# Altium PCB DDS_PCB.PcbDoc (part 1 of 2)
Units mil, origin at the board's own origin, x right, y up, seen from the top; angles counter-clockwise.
Board outline 3998.07 x 3476.44 mil, 8 copper layers (TOP_L1, Plane_L2, Inner_L3, Plane_L4, Plane_L5, Inner_L6, Plane_L7, Bottom Layer_L8), stack 26.8 mil thick; 404 components, 274 nets, 1325 pads, 24 vias.
Unrouted connection lines stored in the file: 923.
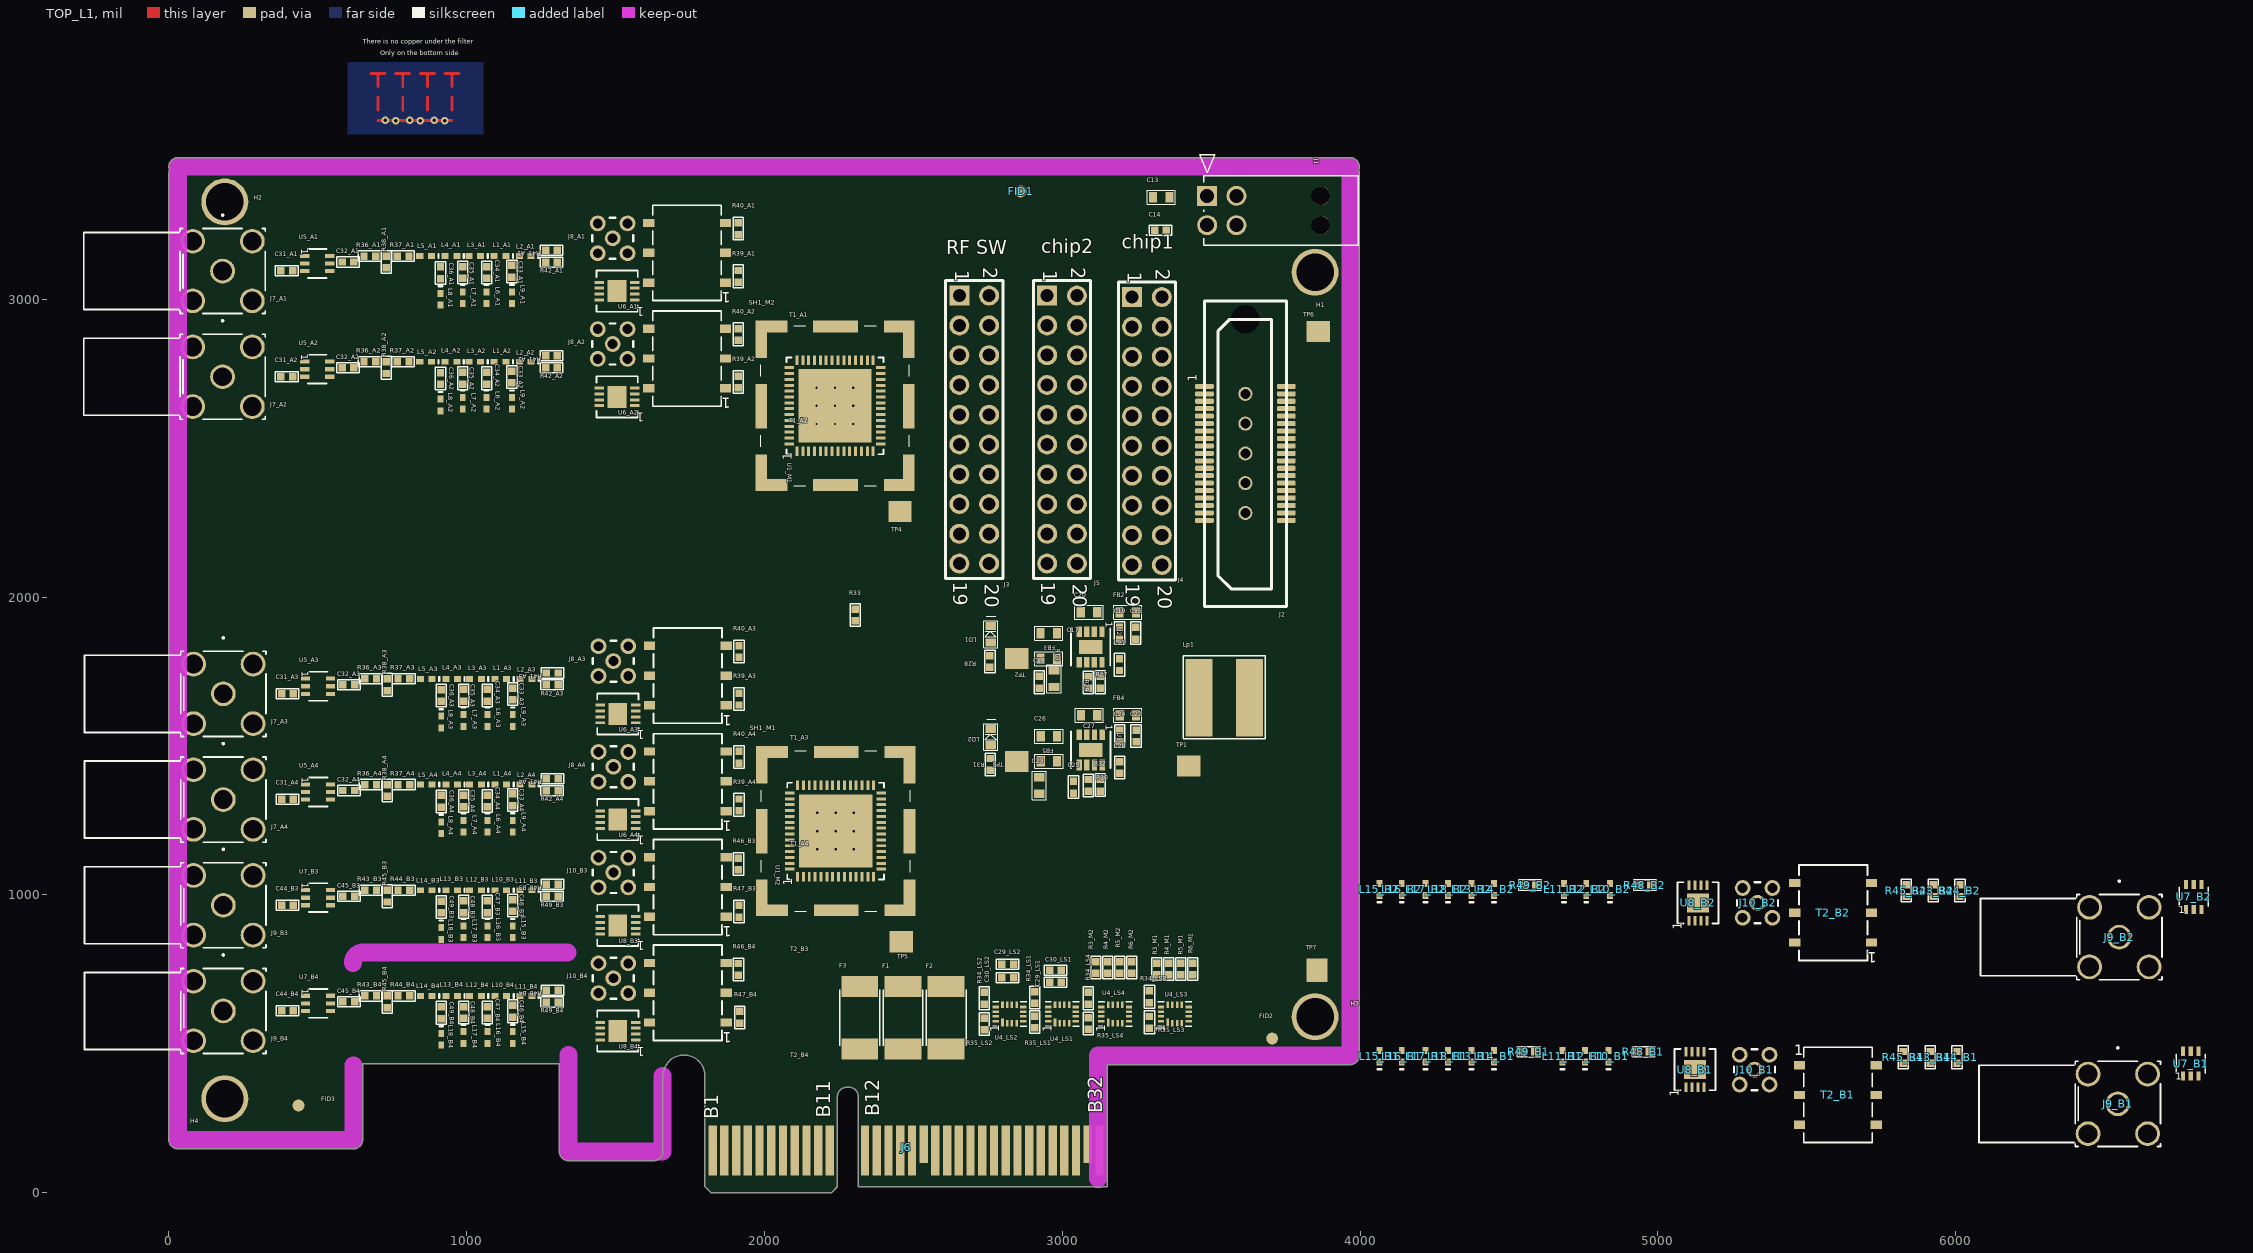
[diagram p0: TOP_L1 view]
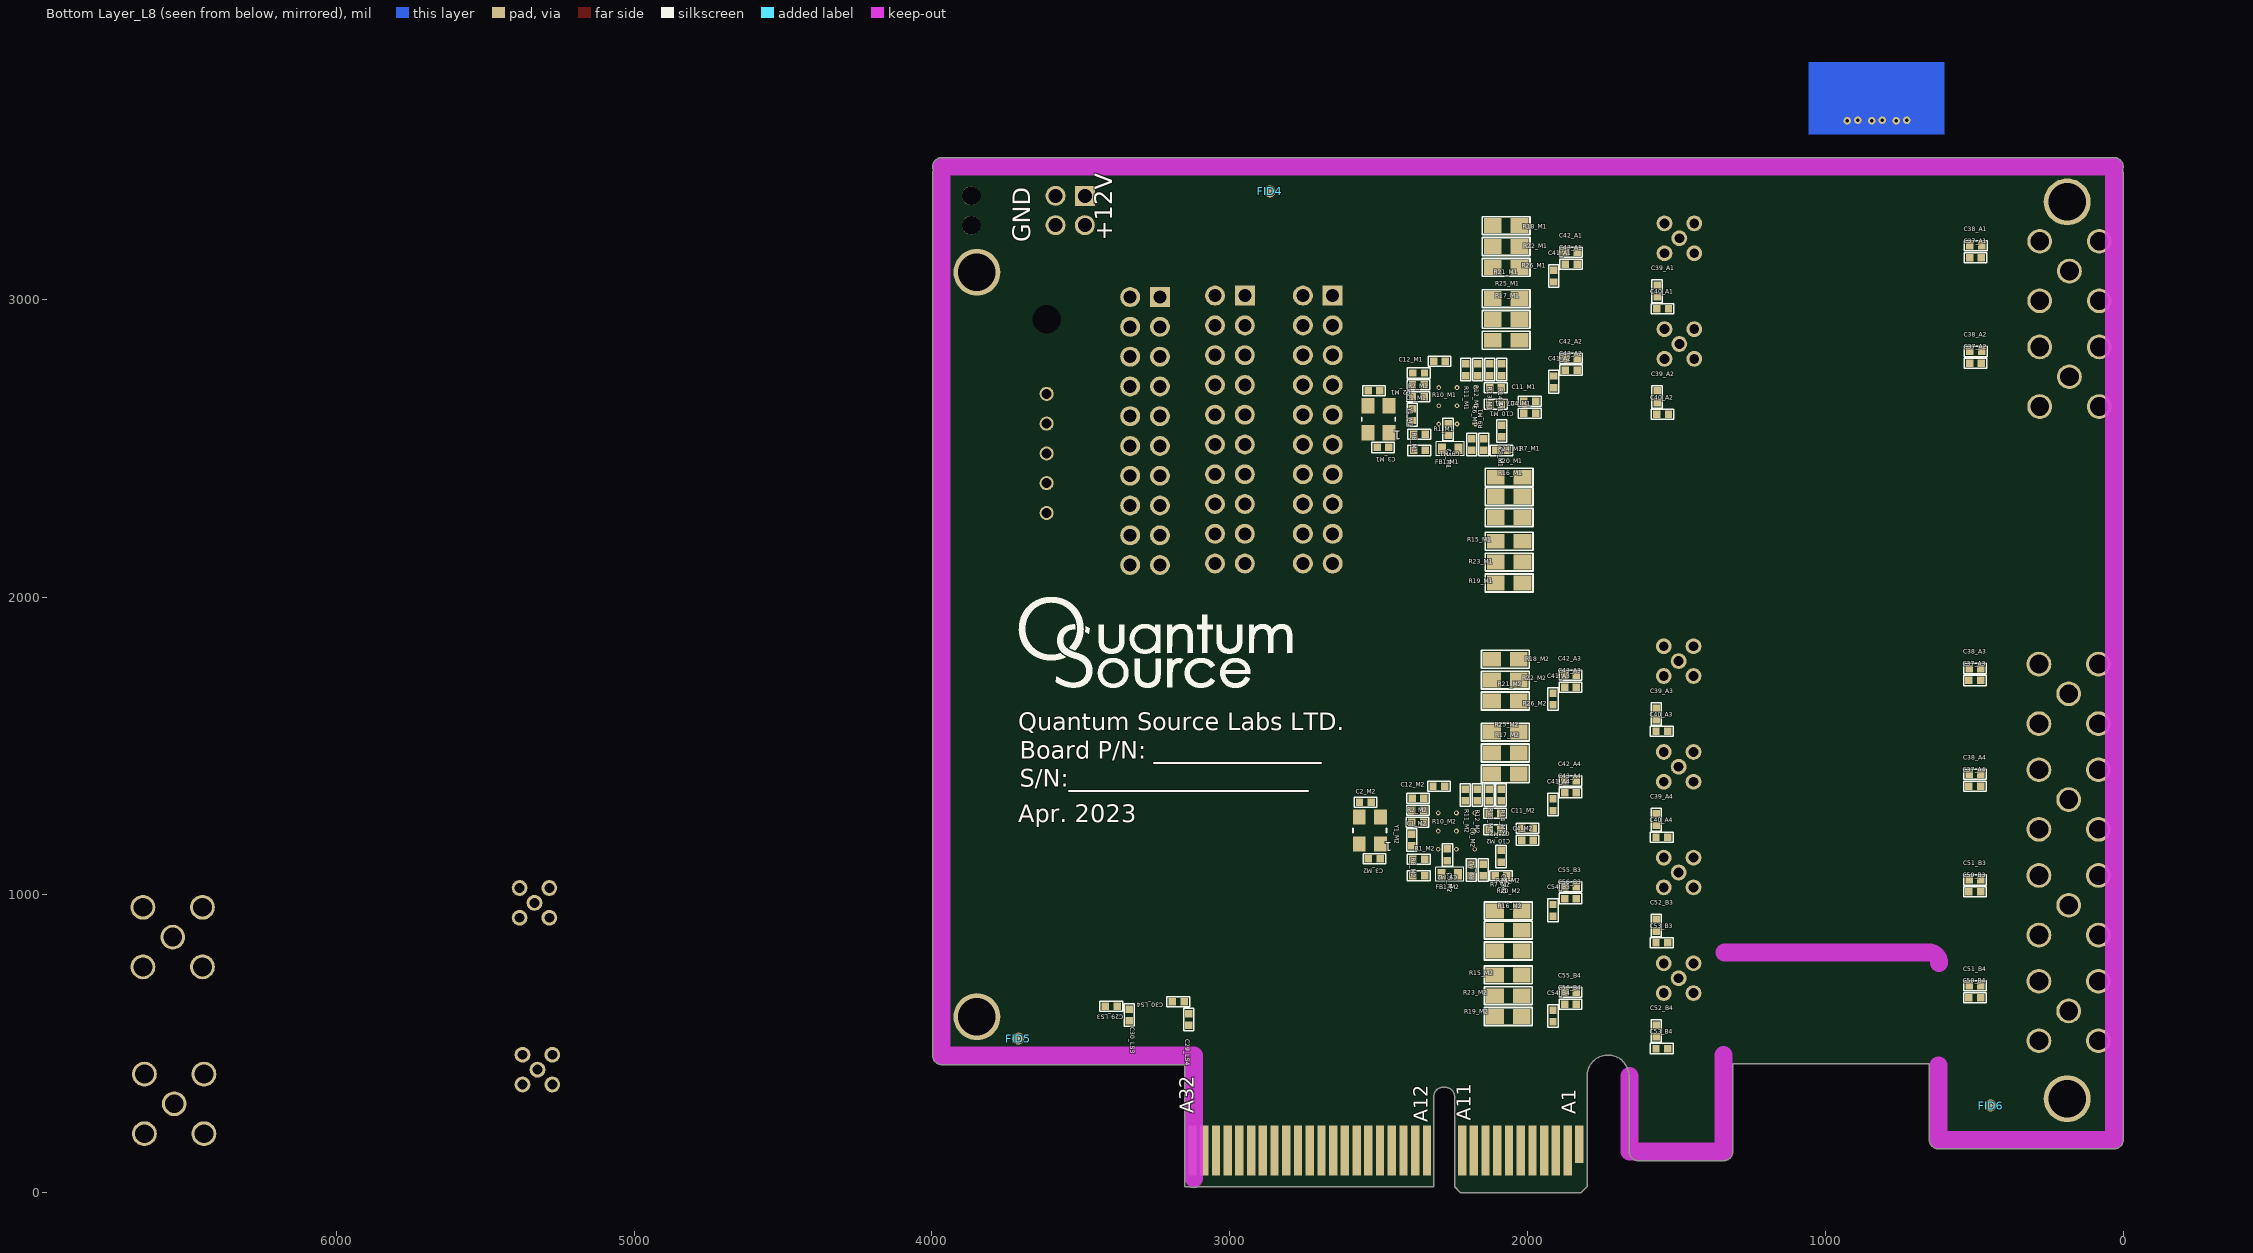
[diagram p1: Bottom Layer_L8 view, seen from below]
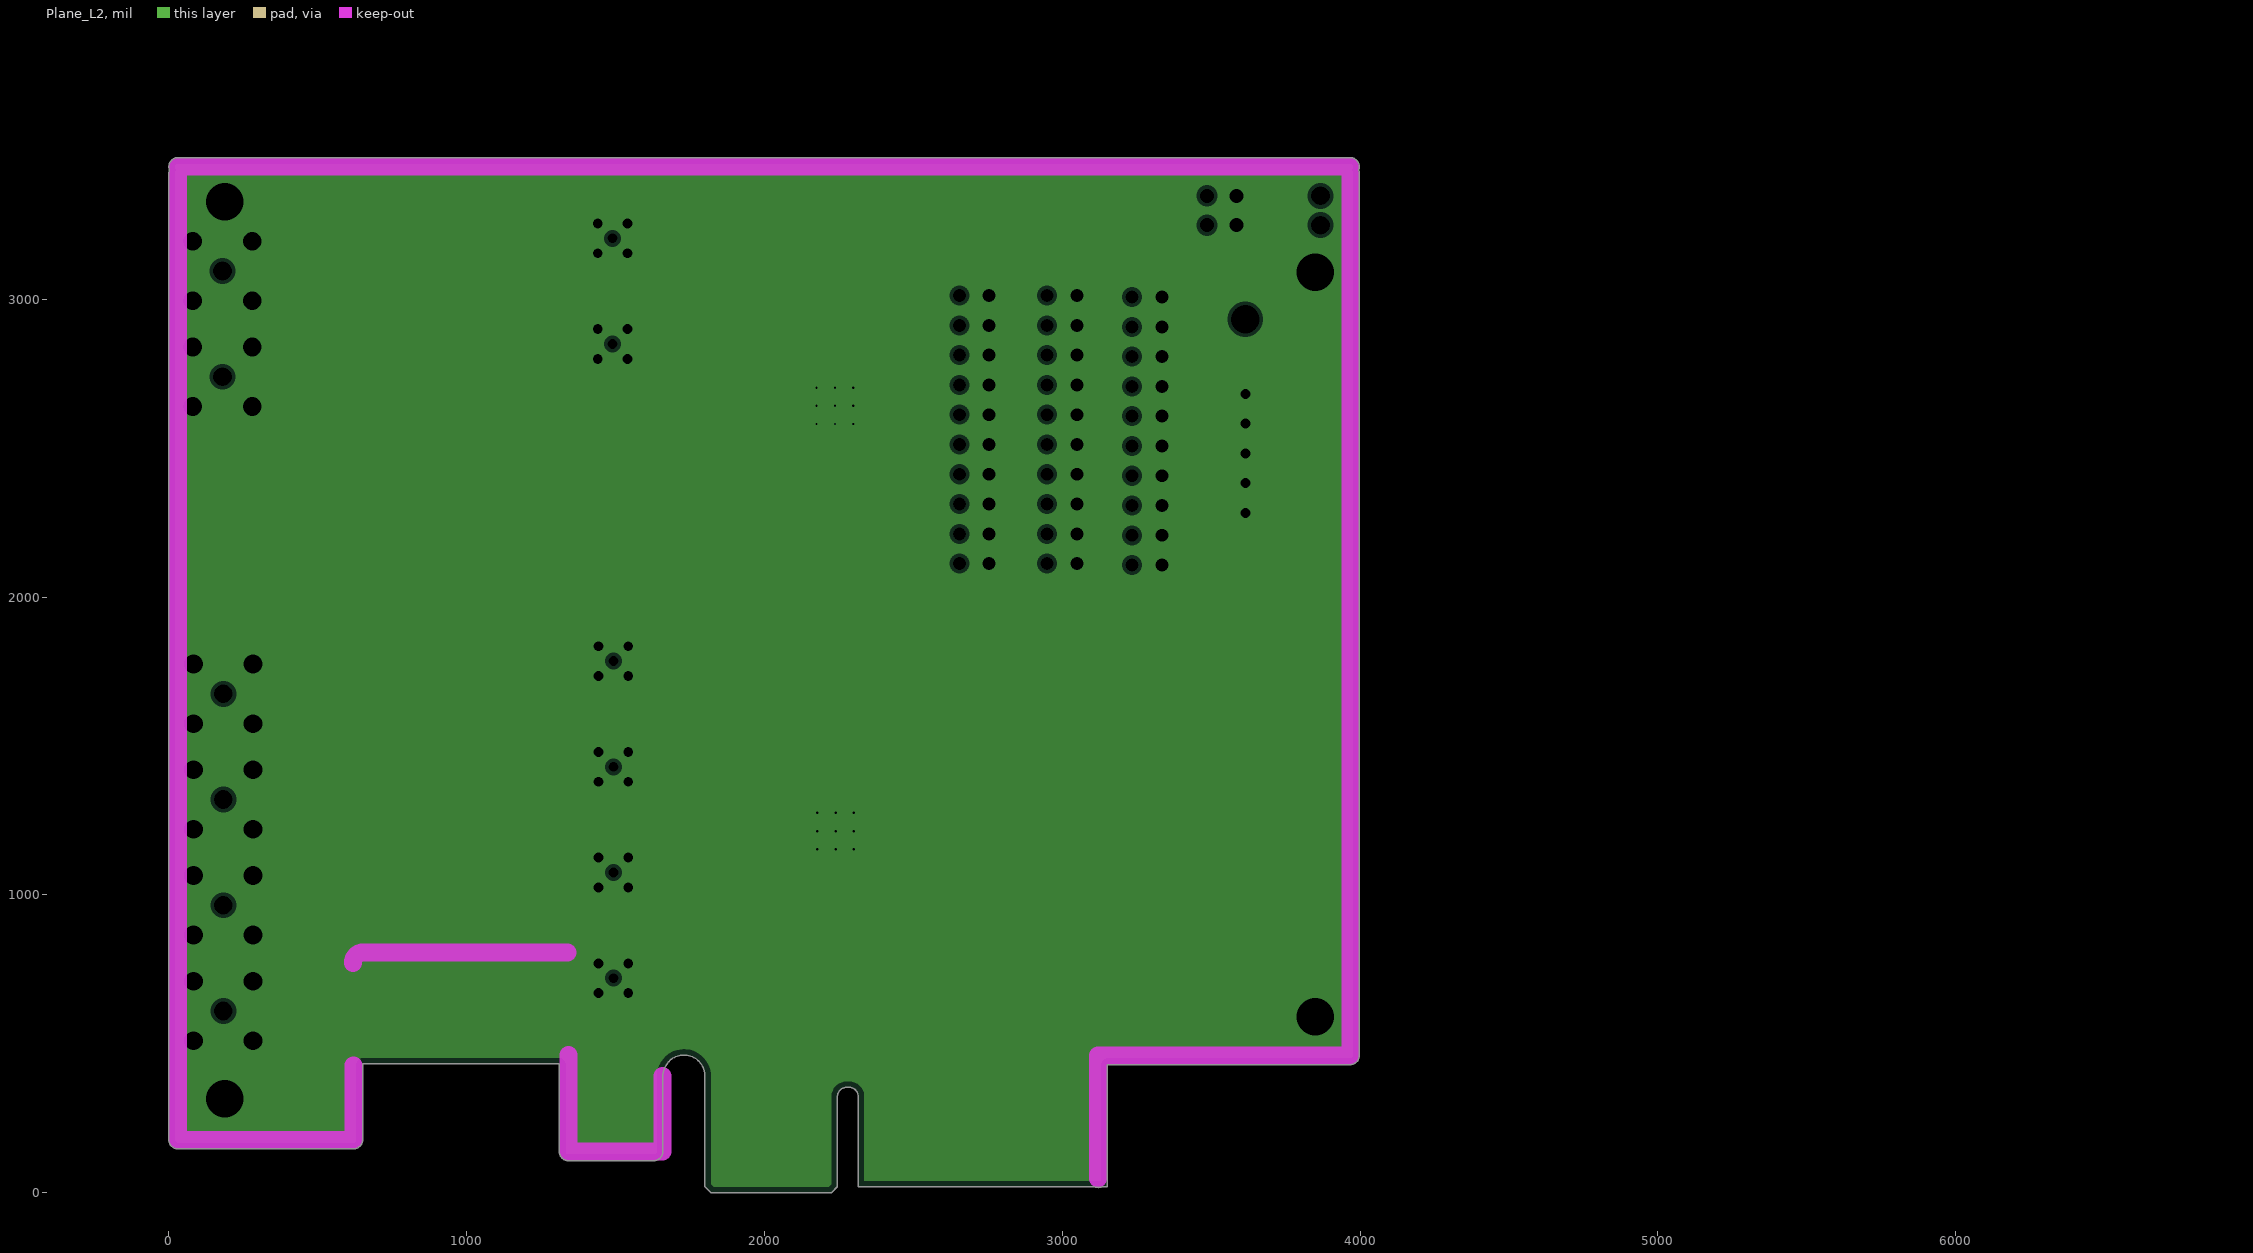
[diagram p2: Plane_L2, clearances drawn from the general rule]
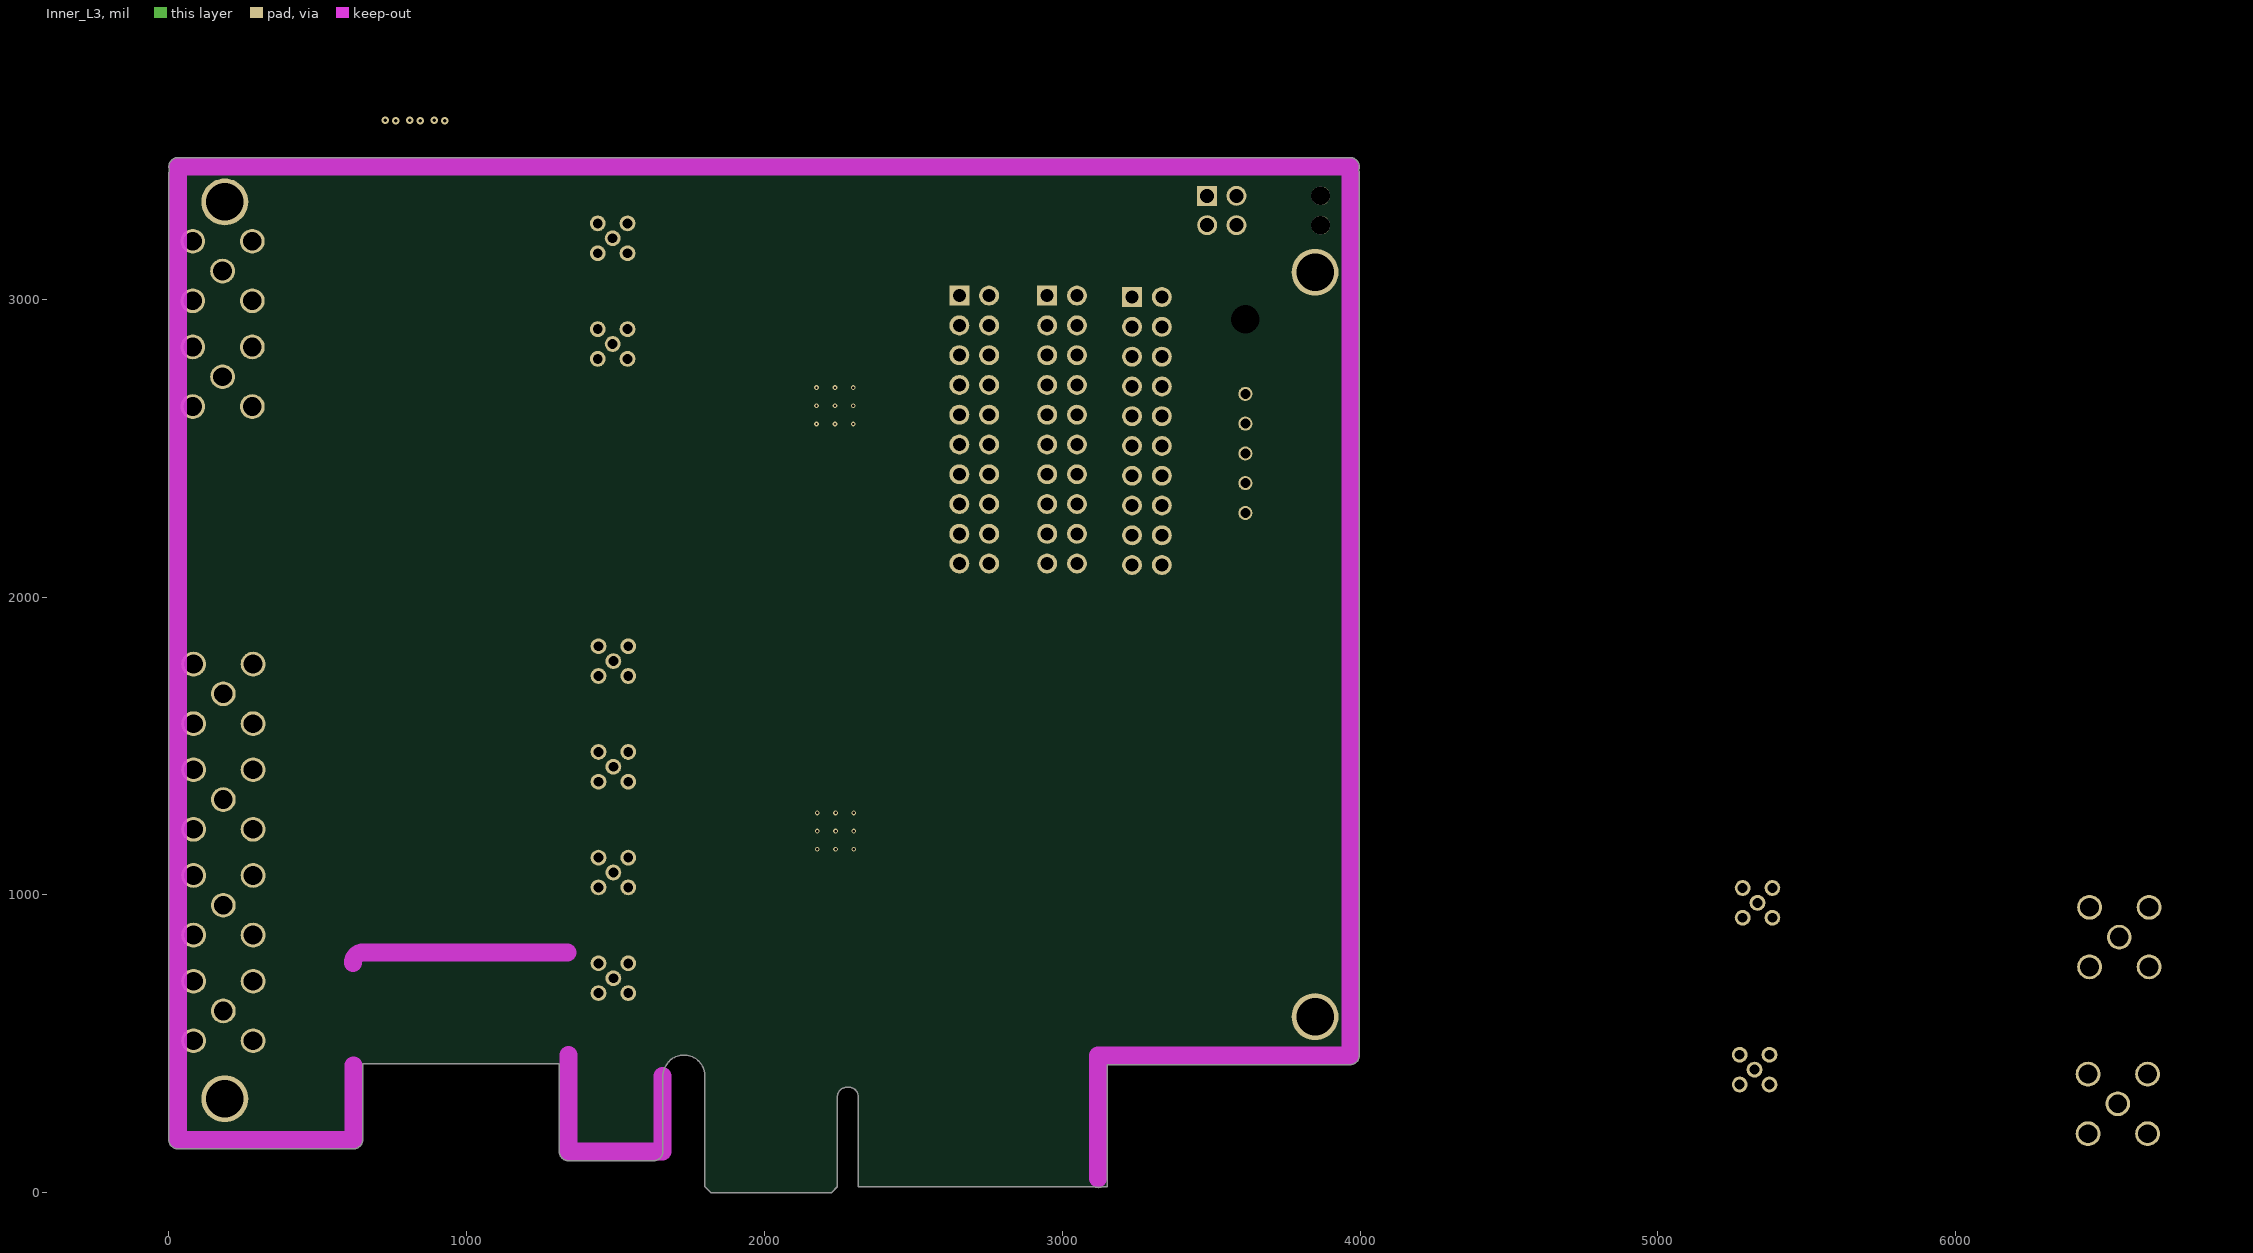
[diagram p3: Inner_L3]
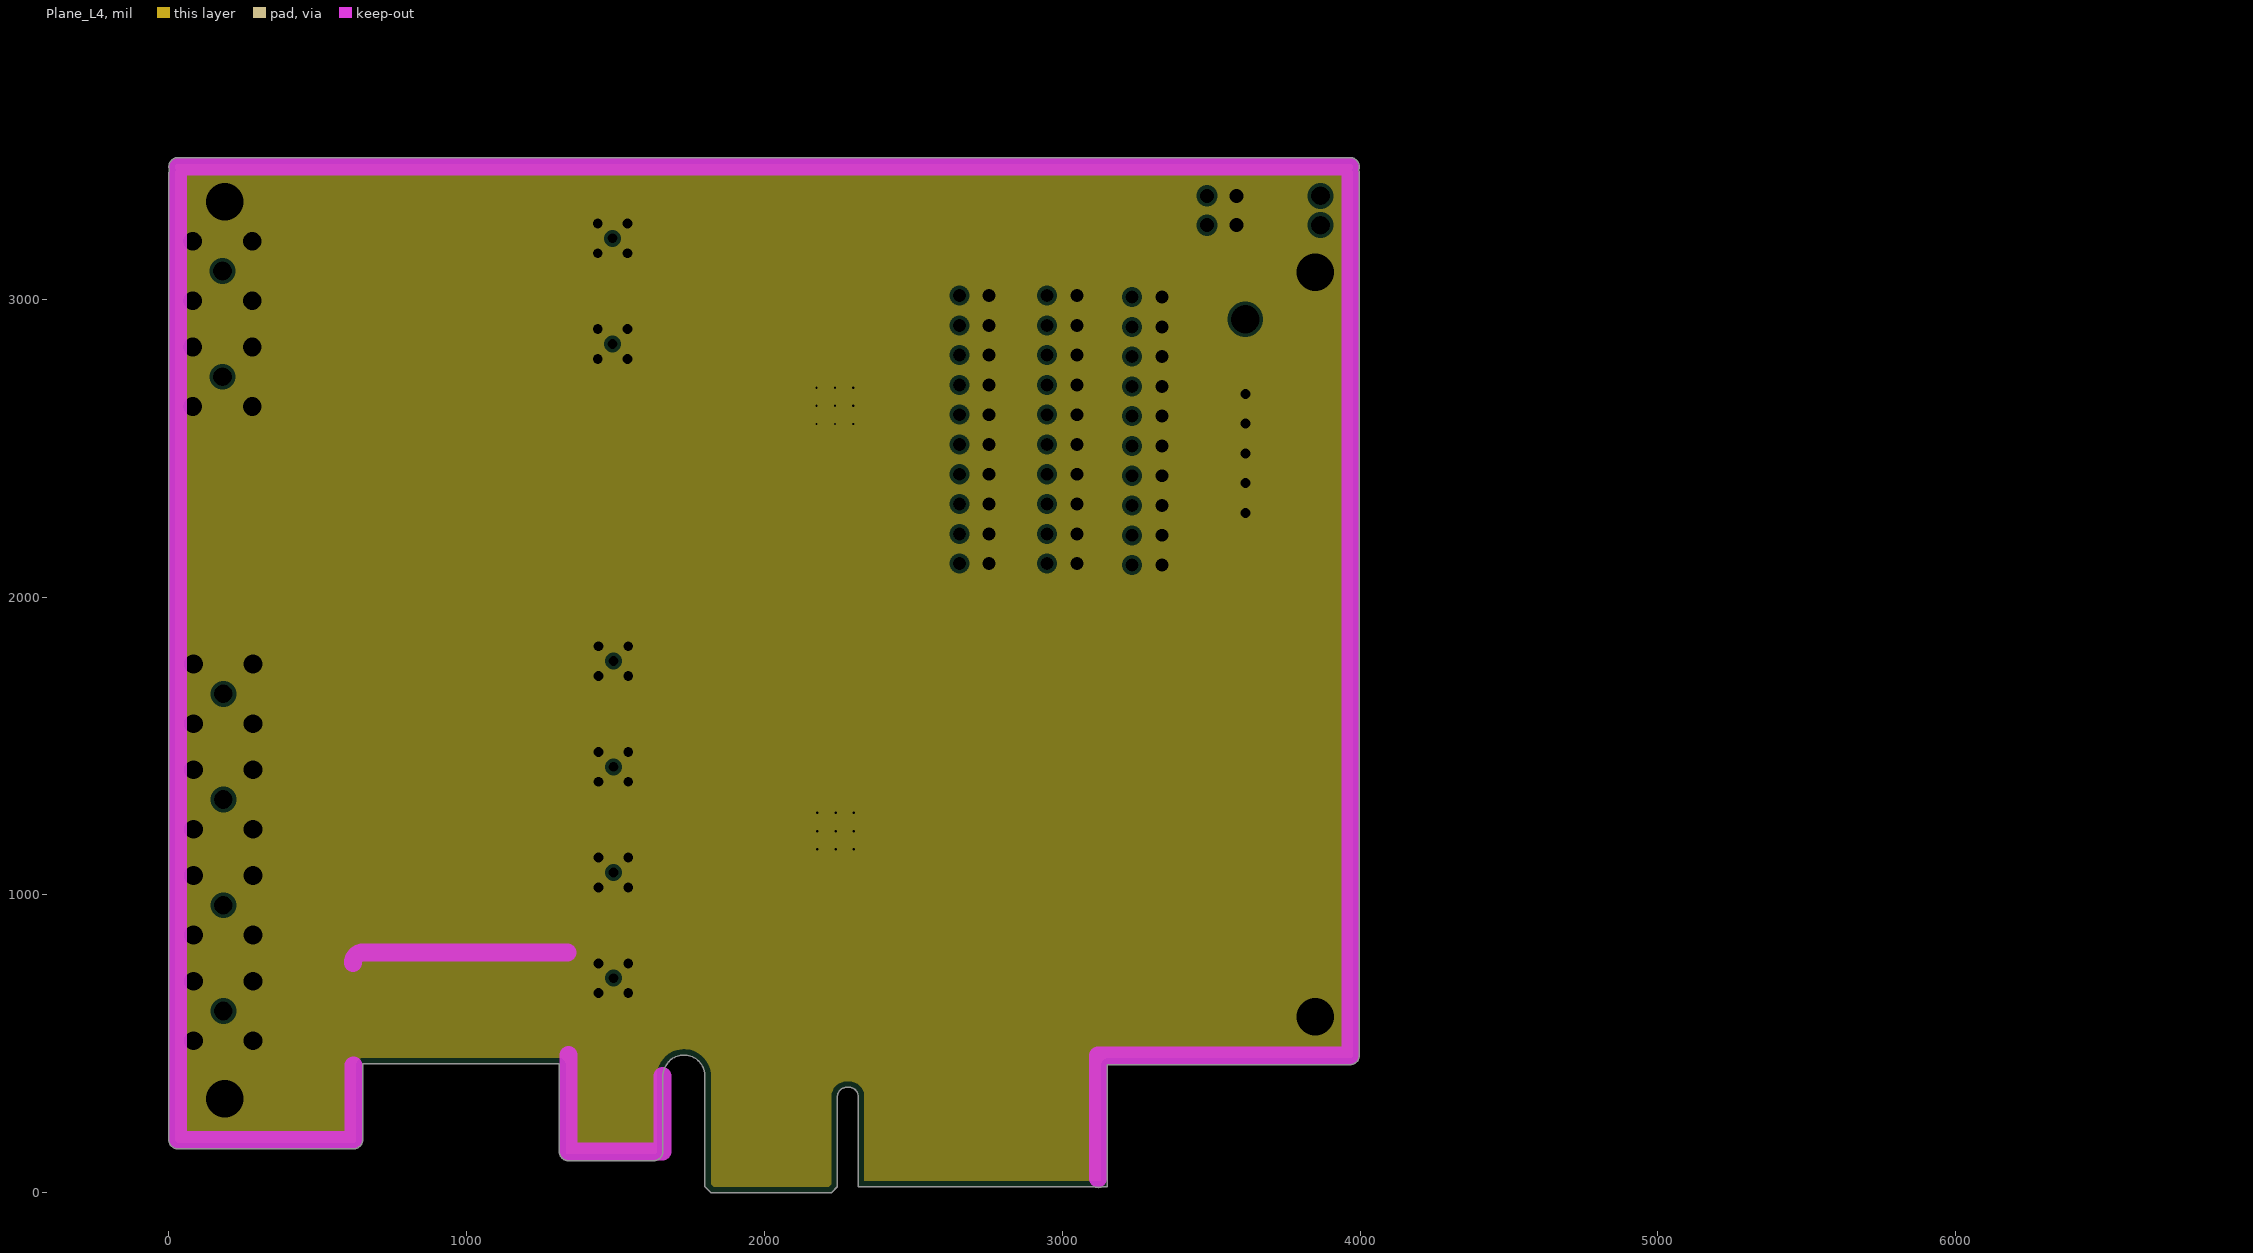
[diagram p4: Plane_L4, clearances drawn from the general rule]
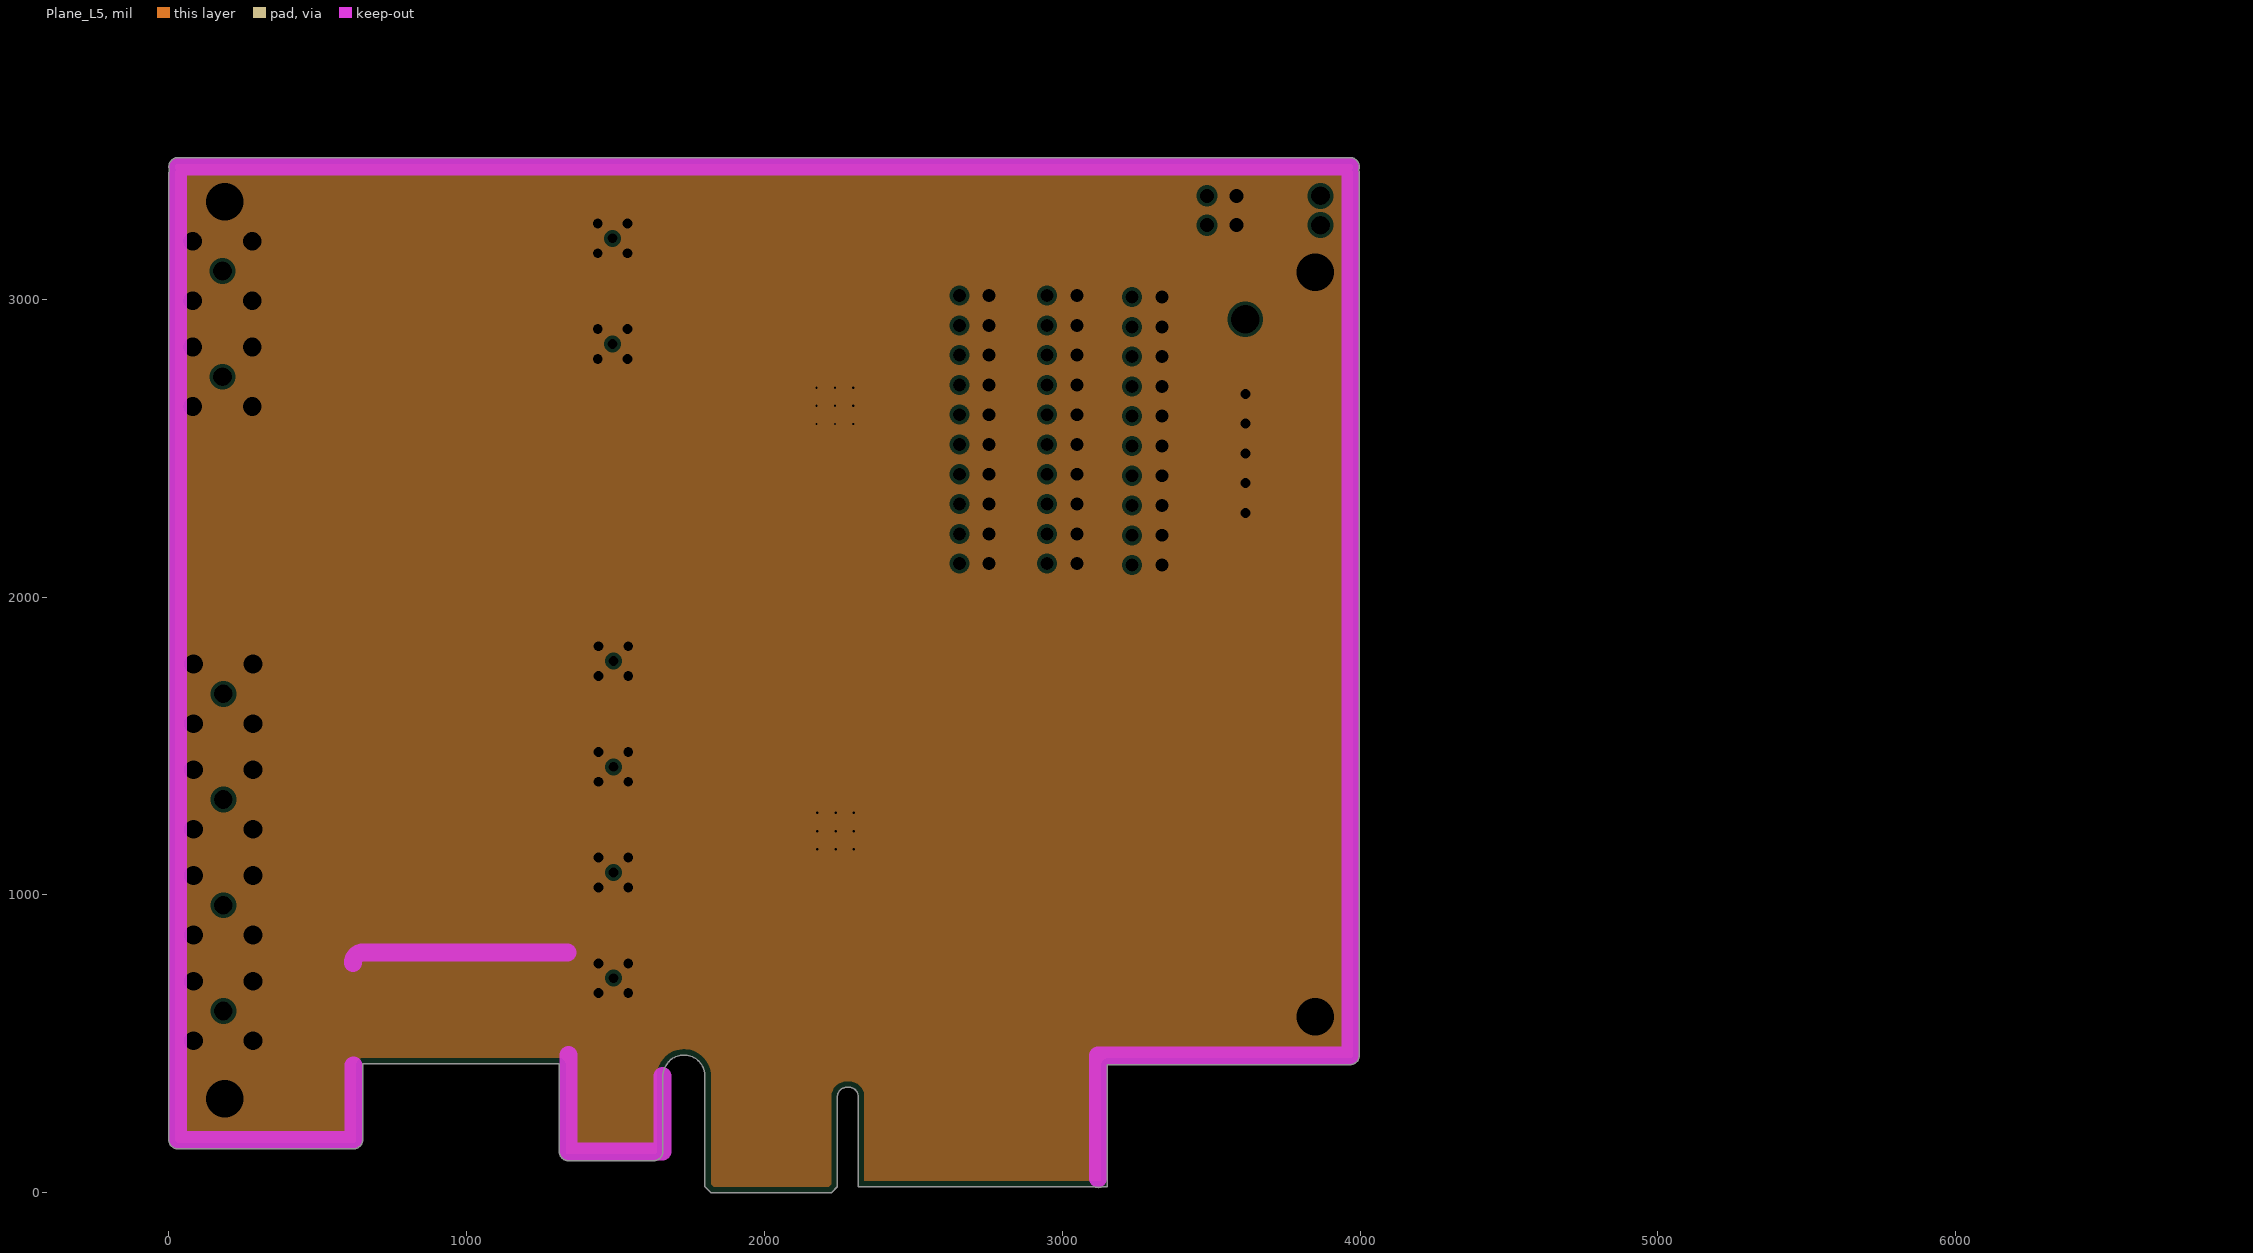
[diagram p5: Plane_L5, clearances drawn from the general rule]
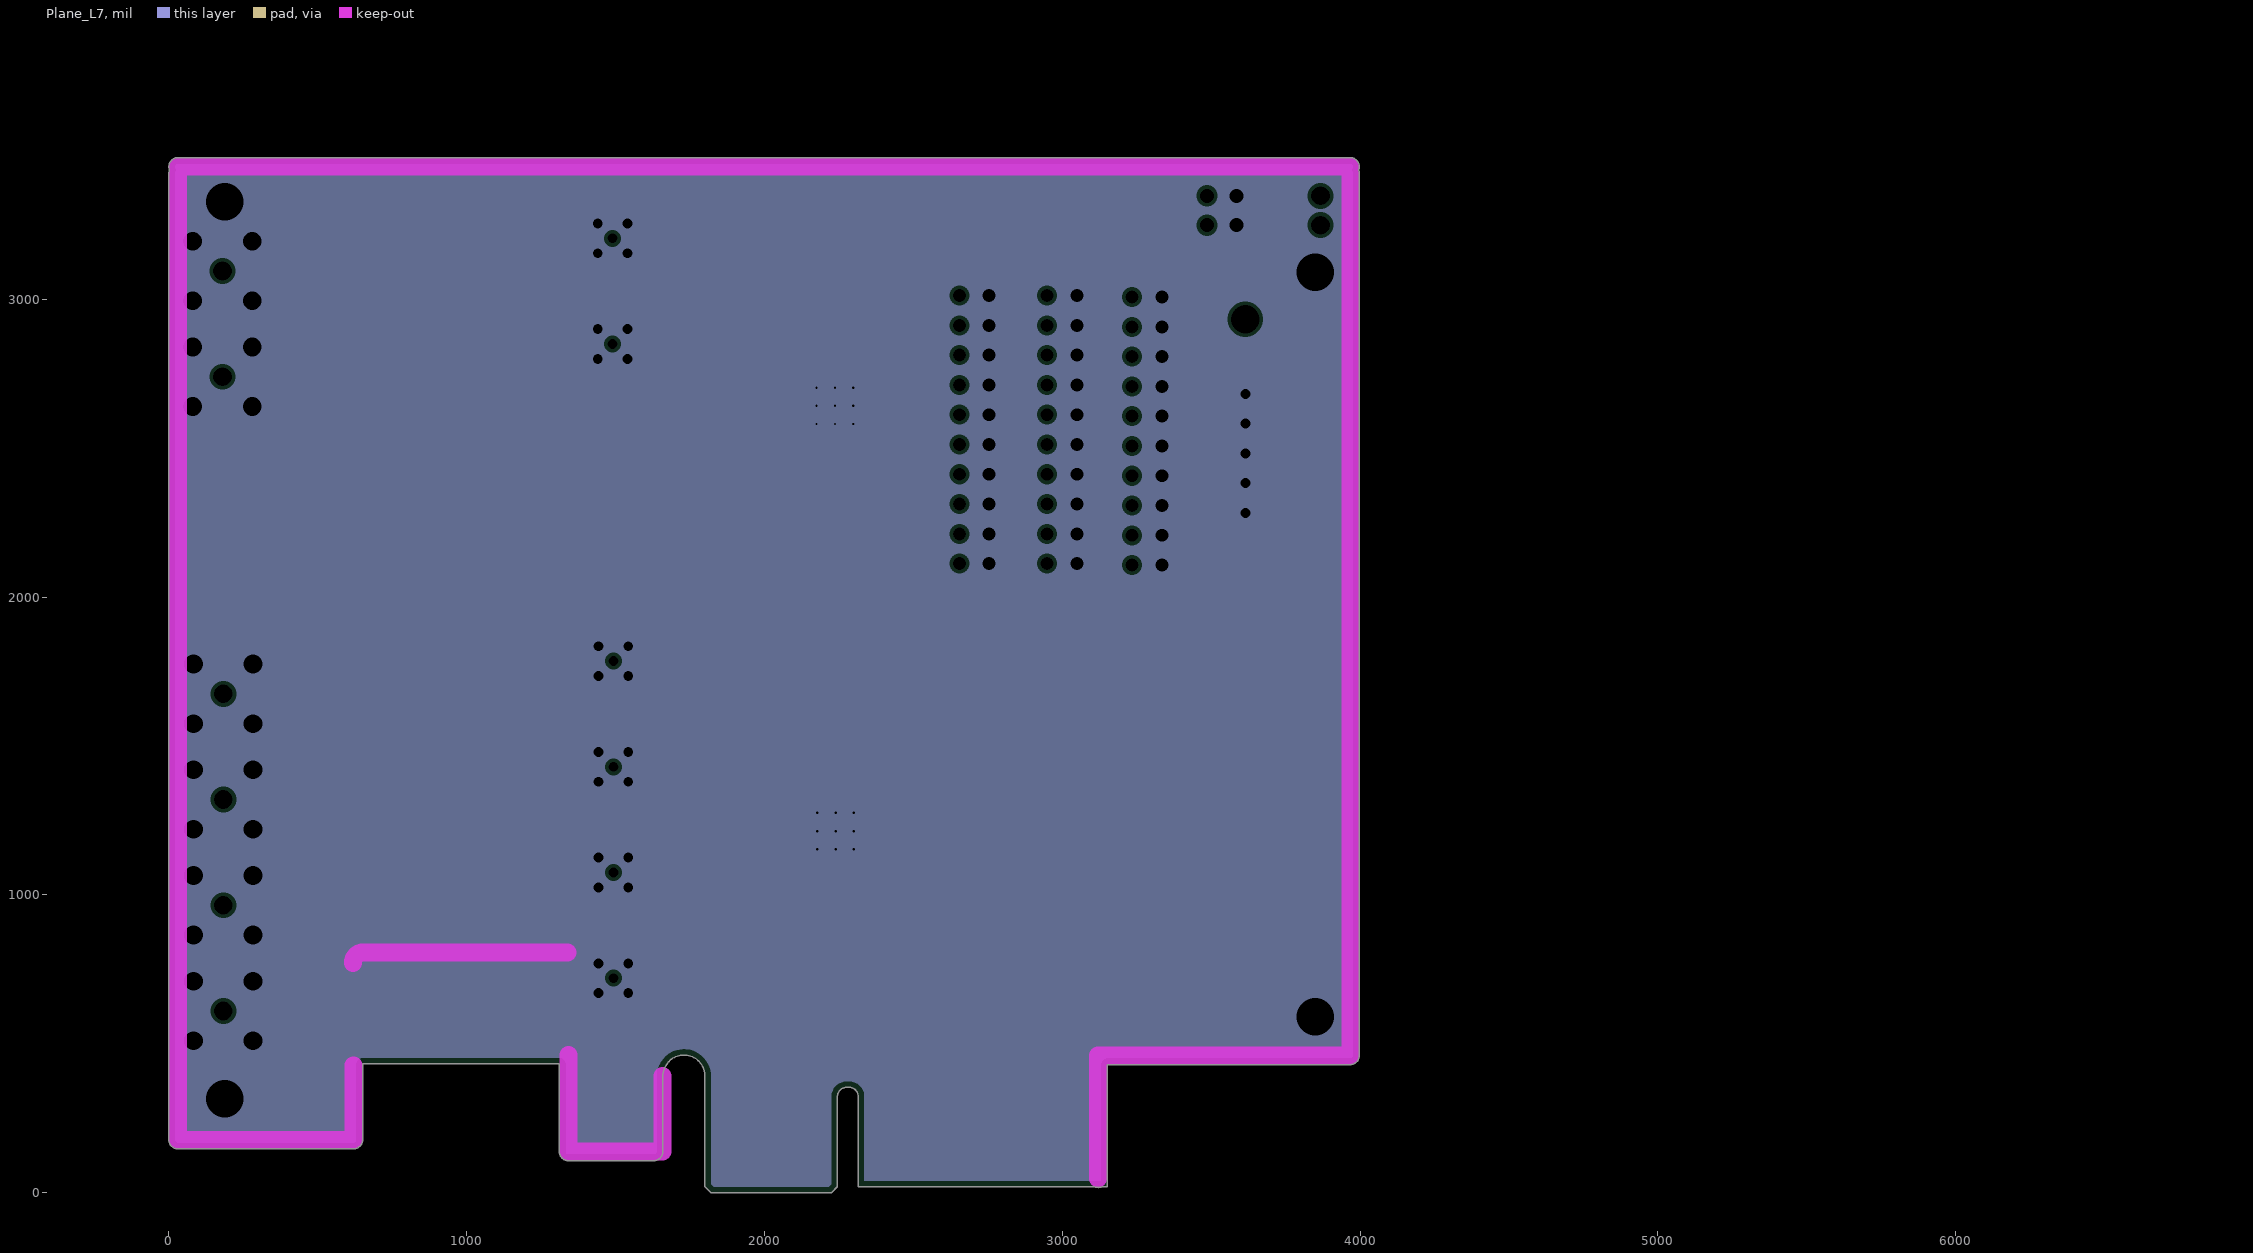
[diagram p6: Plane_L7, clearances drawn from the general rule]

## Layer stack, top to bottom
Top Solder: solder mask 0.4, Solder Resist, Dk 3.5
TOP_L1: signal copper 0.6
Dielectric1: core 2.9, FR-4, Dk 3.2
Plane_L2: plane copper 0.7, net GND
Dielectric7: prepreg 3, FR-4, Dk 3.3
Inner_L3: signal copper 0.7
Dielectric4: core 2.8, FR-4, Dk 3.1
Plane_L4: plane copper 1.2, net GND
Dielectric10: prepreg 3, FR-4, Dk 3.3
Plane_L5: plane copper 1.2, net GND
Dielectric 1: core 2.8, FR-4, Dk 3.1
Inner_L6: signal copper 0.7
Dielectric 6: prepreg 3, FR-4, Dk 3.3
Plane_L7: plane copper 0.7, net GND
Dielectric 7: core 2.9, FR-4, Dk 3.2
Bottom Layer_L8: signal copper 0.6
Board Layer Stack Bottom Solder: solder mask 0.4, Solder Resist, Dk 3.5

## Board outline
30.02,147 cw(c30.02,177.53) -0.51,177.53 -0.51,3422.53 cw(c30.02,3422.53) 1.68,3433.89 cw(c30.02,3445.25) 30.01,3475.78 30.02,3475.78 3967.02,3475.78 cw(c3967.02,3445.25) 3997.55,3445.25 3997.55,3445.24 cw(c3967.02,3445.25) 3995.36,3433.89 cw(c3967.02,3422.53) 3997.55,3422.54 3997.55,3422.53 3997.55,460.41 cw(c3967.02,460.4) 3967.02,429.87 3151.68,429.87 3151.68,20.57 3150.65,19.54 3132.64,19.54 cw(c3120.65,47.61) 3108.65,19.54 2316,19.54 2314.97,20.57 2314.97,322.33 ccw(c2283.83,322.33) 2283.83,353.47 2276.2,353.47 ccw(c2276.2,322.18) 2244.91,322.18 2244.91,20.2 2244.61,19.47 2224.78,-0.36 2224.05,-0.66 1821.35,-0.66 1820.63,-0.36 1800.68,19.38 1800.12,20.35 1800.12,391.24 ccw(c1729.4,391.24) 1729.4,461.96 1729.39,461.96 ccw(c1729.39,392.09) 1665.72,420.87 1665.05,420.6 ccw(c1729.39,391.24) 1658.66,391.24 1658.66,138.36 1658.67,138.28 cw(c1627.63,138.28) 1627.63,107.24 1342.01,107.24 cw(c1342.01,138.28) 1310.96,138.28 1310.96,432.04 650.61,432.04 650.61,178.05 cw(c619.57,178.05) 619.57,147

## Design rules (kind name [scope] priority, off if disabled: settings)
Clearance [All] p1: gap=8 ignorepadtopadclearanceinfootprint=FALSE except(0: Arc-Hole Track-Hole SMDPad-Hole THPad-Hole Via-Hole Fill-Hole Poly-Hole Region-Hole Text-Hole)
DiffPairsRouting DiffPair_100OhmDiffPairsRouting [InDifferentialPairClass('New Class_100Ohm')] p1: maxlimit=6.5 minlimit=6 mostfreqgap=6.5 toplayer_maxgap=6 toplayer_prefgap=6 toplayer_minwidth=15 toplayer_maxwidth=15 toplayer_prefwidth=15 midlayer2_mingap=6.5 midlayer2_minwidth=15 midlayer2_maxwidth=15 midlayer2_prefwidth=15 midlayer4_mingap=6.5 midlayer4_minwidth=15 midlayer4_maxwidth=15 midlayer4_prefwidth=15 bottomlayer_maxgap=6 bottomlayer_prefgap=6 bottomlayer_minwidth=15 bottomlayer_maxwidth=15 bottomlayer_prefwidth=15 maxuncoupledlength=500
Length Length_GPIO2_[0..15] [InNetClass('GPIO2_[0..15]')] p1: maxlimit=1628 minlimit=1600
Length Length_DDR3_A0-15_control [InNetClass('DDR3_A[0..15]_CONTROL')] p2: maxlimit=2401 minlimit=2400
Length Length_SSF_TD1-6 [InDifferentialPairClass('New Class_SSF_TD1-6')] p3: maxlimit=10579 minlimit=10578
Length Length_PCI_RX0-7 [InDifferentialPairClass('New Class_PCI_RX0-6')] p4: maxlimit=2601 minlimit=2600
Length Length_PCI_TX0-7 [InDifferentialPairClass('New Class_PCI_TX0-6')] p5: maxlimit=2016 minlimit=2015
MatchedLengths DiffPair_85OhmMatchedLengths [All] p1: tolerance=25 checknetsindiffpair=TRUE checkdiffpairvsdiffpair=FALSE checkxsignals=FALSE checkothers=FALSE
MatchedLengths DiffPair_80OhmMatchedLengths [All] p2: tolerance=25 checknetsindiffpair=TRUE checkdiffpairvsdiffpair=FALSE checkxsignals=FALSE checkothers=FALSE
MatchedLengths DiffPair_100OhmMatchedLengths [All] p3: tolerance=25 checknetsindiffpair=TRUE checkdiffpairvsdiffpair=FALSE checkxsignals=FALSE checkothers=FALSE
PlaneClearance [All] p1: clearance=12
PlaneConnect PlaneConnect_Via [Isvia] p1: planeconnectstyle=Direct reliefexpansion=20 reliefentries=4 reliefconductorwidth=10 reliefairgap=10
PlaneConnect [All] p2: planeconnectstyle=Relief reliefexpansion=20 reliefentries=4 reliefconductorwidth=20 reliefairgap=8
PolygonConnect PolygonConnect_1PWRPAD [InPadClass('New Class_PWRpad')] p1: connectstyle=Direct reliefconductorwidth=10 reliefentries=4 polygonreliefangle="90 Angle" airgapwidth=10
PolygonConnect PolygonConnect_PWR [InComponentClass('New Class_pwr')] p2: connectstyle=Relief reliefconductorwidth=30 reliefentries=4 polygonreliefangle="90 Angle" airgapwidth=10
PolygonConnect PolygonConnect_Via [Isvia] p3: connectstyle=Direct reliefconductorwidth=10 reliefentries=4 polygonreliefangle="90 Angle" airgapwidth=10
PolygonConnect PolygonConnect_TPs [InComponentClass('New Class_TPs')] p4: connectstyle=Direct reliefconductorwidth=10 reliefentries=4 polygonreliefangle="90 Angle" airgapwidth=10
PolygonConnect [All] p5: connectstyle=Relief reliefconductorwidth=20 reliefentries=4 polygonreliefangle="90 Angle" airgapwidth=10
RoomDefinition B3 [InComponentClass('B3')] p1: confinementstyle=ConfineIn formatcopy=TRUE lockcomponents=FALSE outline -24969.98,-32321.95 -22969.98,-32321.95 -22969.98,-31321.95 -24969.98,-31321.95
RoomDefinition B4 [InComponentClass('B4')] p2: confinementstyle=ConfineIn formatcopy=TRUE lockcomponents=FALSE outline -299.98,438.05 1950.02,438.05 1950.02,848.05 -299.98,848.05
RoomDefinition B1 [InComponentClass('B1')] p3: confinementstyle=ConfineIn formatcopy=TRUE lockcomponents=FALSE outline 4040.02,138.05 6855.02,138.05 6855.02,508.05 4040.02,508.05
RoomDefinition A4 [InComponentClass('A4')] p4: confinementstyle=ConfineIn formatcopy=TRUE lockcomponents=FALSE outline -299.98,1148.05 1945.02,1148.05 1945.02,1558.05 -299.98,1558.05
RoomDefinition A3 [InComponentClass('A3')] p5: confinementstyle=ConfineIn formatcopy=TRUE lockcomponents=FALSE outline -299.98,793.05 1945.02,793.05 1945.02,1203.05 -299.98,1203.05
RoomDefinition B2 [InComponentClass('B2')] p6: confinementstyle=ConfineIn formatcopy=TRUE lockcomponents=FALSE outline -299.98,2568.05 1945.02,2568.05 1945.02,2978.05 -299.98,2978.05
RoomDefinition A2 [InComponentClass('A2')] p7: confinementstyle=ConfineIn formatcopy=TRUE lockcomponents=FALSE outline -299.98,2568.05 1945.02,2568.05 1945.02,2978.05 -299.98,2978.05
RoomDefinition A1 [InComponentClass('A1')] p8: confinementstyle=ConfineIn formatcopy=TRUE lockcomponents=FALSE outline -299.98,2923.05 1945.02,2923.05 1945.02,3333.05 -299.98,3333.05
RoutingVias [All] p1: holewidth=10 width=20 viastyle="Through Hole" minholewidth=10 minwidth=20 maxholewidth=28 maxwidth=50
SilkToSolderMaskClearance SilkscreenOverComponentPads [IsPad] p1: minsilkscreentomaskgap=10 clearancetoexposedcopper=TRUE
SolderMaskExpansion [All] p1: expansion=4 istentingtop=FALSE
Width [All] p1: maxlimit=100 minlimit=6 preferedwidth=8
26 further rules are at their usual default settings.

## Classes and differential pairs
component class B4: C44_B4 C45_B4 C46_B4 C47_B4 C48_B4 C49_B4 C50_B4 C51_B4 C52_B4 C53_B4 C54_B4 C55_B4 C56_B4 J9_B4 J10_B4 L10_B4 L11_B4 L12_B4 L13_B4 L14_B4 L15_B4 L16_B4 L17_B4 L18_B4 R43_B4 R44_B4 R45_B4 R46_B4 R47_B4 R48_B4 R49_B4 T2_B4 U7_B4 U8_B4
component class B2: C44_B2 C45_B2 C46_B2 C47_B2 C48_B2 C49_B2 C50_B2 C51_B2 C52_B2 C53_B2 C54_B2 C55_B2 C56_B2 J9_B2 J10_B2 L10_B2 L11_B2 L12_B2 L13_B2 L14_B2 L15_B2 L16_B2 L17_B2 L18_B2 R43_B2 R44_B2 R45_B2 R46_B2 R47_B2 R48_B2 R49_B2 T2_B2 U7_B2 U8_B2
component class B1: C44_B1 C45_B1 C46_B1 C47_B1 C48_B1 C49_B1 C50_B1 C51_B1 C52_B1 C53_B1 C54_B1 C55_B1 C56_B1 J9_B1 J10_B1 L10_B1 L11_B1 L12_B1 L13_B1 L14_B1 L15_B1 L16_B1 L17_B1 L18_B1 R43_B1 R44_B1 R45_B1 R46_B1 R47_B1 R48_B1 R49_B1 T2_B1 U7_B1 U8_B1
component class A3: C31_A3 C32_A3 C33_A3 C34_A3 C35_A3 C36_A3 C37_A3 C38_A3 C39_A3 C40_A3 C41_A3 C42_A3 C43_A3 J7_A3 J8_A3 L1_A3 L2_A3 L3_A3 L4_A3 L5_A3 L6_A3 L7_A3 L8_A3 L9_A3 R36_A3 R37_A3 R38_A3 R39_A3 R40_A3 R41_A3 R42_A3 T1_A3 U5_A3 U6_A3
channel class analog_channel3: B1 B2 B3 B4
component class A4: C31_A4 C32_A4 C33_A4 C34_A4 C35_A4 C36_A4 C37_A4 C38_A4 C39_A4 C40_A4 C41_A4 C42_A4 C43_A4 J7_A4 J8_A4 L1_A4 L2_A4 L3_A4 L4_A4 L5_A4 L6_A4 L7_A4 L8_A4 L9_A4 R36_A4 R37_A4 R38_A4 R39_A4 R40_A4 R41_A4 R42_A4 T1_A4 U5_A4 U6_A4
component class B3: C44_B3 C45_B3 C46_B3 C47_B3 C48_B3 C49_B3 C50_B3 C51_B3 C52_B3 C53_B3 C54_B3 C55_B3 C56_B3 J9_B3 J10_B3 L10_B3 L11_B3 L12_B3 L13_B3 L14_B3 L15_B3 L16_B3 L17_B3 L18_B3 R43_B3 R44_B3 R45_B3 R46_B3 R47_B3 R48_B3 R49_B3 T2_B3 U7_B3 U8_B3
component class A2: C31_A2 C32_A2 C33_A2 C34_A2 C35_A2 C36_A2 C37_A2 C38_A2 C39_A2 C40_A2 C41_A2 C42_A2 C43_A2 J7_A2 J8_A2 L1_A2 L2_A2 L3_A2 L4_A2 L5_A2 L6_A2 L7_A2 L8_A2 L9_A2 R36_A2 R37_A2 R38_A2 R39_A2 R40_A2 R41_A2 R42_A2 T1_A2 U5_A2 U6_A2
component class A1: C31_A1 C32_A1 C33_A1 C34_A1 C35_A1 C36_A1 C37_A1 C38_A1 C39_A1 C40_A1 C41_A1 C42_A1 C43_A1 J7_A1 J8_A1 L1_A1 L2_A1 L3_A1 L4_A1 L5_A1 L6_A1 L7_A1 L8_A1 L9_A1 R36_A1 R37_A1 R38_A1 R39_A1 R40_A1 R41_A1 R42_A1 T1_A1 U5_A1 U6_A1
channel class analog_channel: A1 A2 A3 A4
channel class "Level Shifter": LS1 LS2 LS3 LS4
channel class main: M1 M2
differential pair CH_3_M2: +CH__P3_M2 -CH__N3_M2
differential pair CH_3_M1: +CH__P3_M1 -CH__N3_M1
differential pair CH_2_M2: +CH__P2_M2 -CH__N2_M2
differential pair CH_2_M1: +CH__P2_M1 -CH__N2_M1
differential pair CH1_M2: +CH_P1_M2 -CH_N1_M2
differential pair CH1_M1: +CH_P1_M1 -CH_N1_M1
differential pair CH0_M2: +CH_P0_M2 -CH_N0_M2
differential pair CH0_M1: +CH_P0_M1 -CH_N0_M1

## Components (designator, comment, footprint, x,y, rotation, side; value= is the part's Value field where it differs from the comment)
C1_M1 "680pF 50V" C0402 2367.75,2712.52 r180 bottom (schematic designator C1)
C1_M2 "680pF 50V" C0402 2369.8,1284.11 r180 bottom (schematic designator C1)
C2_M1 "39pF 50V" C0402 2516.47,2692.52 r180 bottom (schematic designator C2)
C2_M2 "39pF 50V" C0402 2545.82,1311.27 r180 bottom (schematic designator C2)
C3_M1 "39pF 50V" C0402 2486.47,2502.52 r180 bottom (schematic designator C3)
C3_M2 "39pF 50V" C0402 2515.82,1121.27 r180 bottom (schematic designator C3)
C4_M1 "1uF 25V" C0402 2108.35,2647.52 r180 bottom (schematic designator C4)
C4_M2 "1uF 25V" C0402 2110.4,1219.11 r180 bottom (schematic designator C4)
C5_M1 "1uF 25V" C0402 2266.85,2564.02 r270 bottom (schematic designator C5)
C5_M2 "1uF 25V" C0402 2268.9,1135.61 r270 bottom (schematic designator C5)
C6_M1 "1uF 25V" C0402 2186.85,2513.42 r270 bottom (schematic designator C6)
C6_M2 "1uF 25V" C0402 2188.9,1085.01 r270 bottom (schematic designator C6)
C7_M1 "10uF 10V" C0402 1990.97,2657.5 r0 bottom (schematic designator C7)
C7_M2 "10uF 10V" C0402 1998.49,1223.76 r0 bottom (schematic designator C7)
C8_M1 "10uF 10V" C0402 2086.85,2559.02 r270 bottom (schematic designator C8)
C8_M2 "10uF 10V" C0402 2088.9,1130.61 r270 bottom (schematic designator C8)
C9_M1 "10uF 10V" C0402 2361.85,2492.52 r0 bottom (schematic designator C9)
C9_M2 "10uF 10V" C0402 2363.9,1064.11 r0 bottom (schematic designator C9)
C10_M1 "0.1uF 50V" C0402 1990.97,2617.5 r0 bottom (schematic designator C10)
C10_M2 "0.1uF 50V" C0402 1998.49,1183.76 r0 bottom (schematic designator C10)
C11_M1 "0.1uF 50V" C0402 2108.35,2702.52 r180 bottom (schematic designator C11)
C11_M2 "0.1uF 50V" C0402 2110.4,1274.11 r180 bottom (schematic designator C11)
C12_M1 "0.1uF 50V" C0402 2296.85,2792.52 r180 bottom (schematic designator C12)
C12_M2 "0.1uF 50V" C0402 2298.9,1364.11 r180 bottom (schematic designator C12)
C13 "10uF 25V" C0603 3332.46,3342.53 r0 top
C14 "10nF 25V" C0402 3328.52,3232.53 r0 top
C15 "10nF 25V" C0402 3247.2,1877.52 r90 top
C16 "22uF 16V" C0603 2972.2,1725.86 r90 top
C17 "22uF 16V" C0603 2954.65,1878.42 r0 top
C18 "10nF 25V" C0402 2922.2,1712.52 r90 top
C19 "10nF 25V" C0402 3192.2,1877.52 r90 top
C20 "10uF 25V" C0603 3089.65,1948.42 r0 top
C21 "NA" C0402 3192.2,1774.32 r270 top
C22 "10nF 25V" C0402 3247.85,1532.08 r90 top
C23 "22uF 16V" C0603 2922.85,1367.08 r90 top
C24 "10nF 25V" C0402 3192.85,1532.08 r90 top
C25 "10nF 25V" C0402 3037.85,1360.42 r90 top
C26 "10uF 25V" C0603 2955.29,1532.98 r0 top
C27 "22uF 16V" C0603 3090.29,1602.98 r0 top
C28 "NA" C0402 3192.85,1428.88 r270 top
C29_LS1 "0.1uF 50V" C0402 2978.79,706.43 r180 top (schematic designator C29)
C29_LS2 "0.1uF 50V" C0402 2817.89,766.43 r180 top (schematic designator C29)
C29_LS3 "0.1uF 50V" C0402 3399.39,626.43 r180 bottom (schematic designator C29)
C29_LS4 "0.1uF 50V" C0402 3137.89,579.93 r90 bottom (schematic designator C29)
C30_LS1 "0.1uF 50V" C0402 2978.79,746.43 r180 top (schematic designator C30)
C30_LS2 "0.1uF 50V" C0402 2817.89,721.43 r180 top (schematic designator C30)
C30_LS3 "0.1uF 50V" C0402 3337.89,594.93 r90 bottom (schematic designator C30)
C30_LS4 "0.1uF 50V" C0402 3174.39,641.43 r180 bottom (schematic designator C30)
C31_A1 "1uF 25V" C0402 394.1,3095.43 r0 top (schematic designator C31)
C31_A2 "1uF 25V" C0402 394.1,2740.43 r0 top (schematic designator C31)
C31_A3 "1uF 25V" C0402 396.62,1675.44 r0 top (schematic designator C31)
C31_A4 "1uF 25V" C0402 396.62,1320.44 r0 top (schematic designator C31)
C32_A1 "1uF 25V" C0402 599.98,3125.41 r0 top (schematic designator C32)
C32_A2 "1uF 25V" C0402 599.98,2770.41 r0 top (schematic designator C32)
C32_A3 "1uF 25V" C0402 602.5,1705.42 r0 top (schematic designator C32)
C32_A4 "1uF 25V" C0402 602.5,1350.42 r0 top (schematic designator C32)
C33_A1 "16pF 50V" C0402 1151.83,3095.41 r270 top (schematic designator C33)
C33_A2 "16pF 50V" C0402 1151.83,2740.41 r270 top (schematic designator C33)
C33_A3 "16pF 50V" C0402 1154.35,1675.42 r270 top (schematic designator C33)
C33_A4 "16pF 50V" C0402 1154.35,1320.42 r270 top (schematic designator C33)
C34_A1 "11pF 50V" C0402 1066.83,3091.31 r270 top (schematic designator C34)
C34_A2 "11pF 50V" C0402 1066.83,2736.31 r270 top (schematic designator C34)
C34_A3 "11pF 50V" C0402 1069.35,1671.32 r270 top (schematic designator C34)
C34_A4 "11pF 50V" C0402 1069.35,1316.32 r270 top (schematic designator C34)
C35_A1 "10pF 50V" C0402 986.83,3091.31 r270 top (schematic designator C35)
C35_A2 "10pF 50V" C0402 986.83,2736.31 r270 top (schematic designator C35)
C35_A3 "10pF 50V" C0402 989.35,1671.32 r270 top (schematic designator C35)
C35_A4 "10pF 50V" C0402 989.35,1316.32 r270 top (schematic designator C35)
C36_A1 "13pF 50V" C0402 911.83,3090.41 r270 top (schematic designator C36)
C36_A2 "13pF 50V" C0402 911.83,2735.41 r270 top (schematic designator C36)
C36_A3 "13pF 50V" C0402 914.35,1670.42 r270 top (schematic designator C36)
C36_A4 "13pF 50V" C0402 914.35,1315.42 r270 top (schematic designator C36)
C37_A1 "1uF 25V" C0402 496.5,3140 r180 bottom (schematic designator C37)
C37_A2 "1uF 25V" C0402 496.5,2785 r180 bottom (schematic designator C37)
C37_A3 "1uF 25V" C0402 499.02,1720.01 r180 bottom (schematic designator C37)
C37_A4 "1uF 25V" C0402 499.02,1365.01 r180 bottom (schematic designator C37)
C38_A1 "0.1uF 50V" C0402 495.9,3180 r180 bottom (schematic designator C38)
C38_A2 "0.1uF 50V" C0402 495.9,2825 r180 bottom (schematic designator C38)
C38_A3 "0.1uF 50V" C0402 498.42,1760.01 r180 bottom (schematic designator C38)
C38_A4 "0.1uF 50V" C0402 498.42,1405.01 r180 bottom (schematic designator C38)
C39_A1 "0.1uF 50V" C0402 1565,3028.82 r270 bottom (schematic designator C39)
C39_A2 "0.1uF 50V" C0402 1565,2673.82 r270 bottom (schematic designator C39)
C39_A3 "0.1uF 50V" C0402 1567.52,1608.82 r270 bottom (schematic designator C39)
C39_A4 "0.1uF 50V" C0402 1567.52,1253.82 r270 bottom (schematic designator C39)
C40_A1 "1uF 25V" C0402 1545,2968.82 r0 bottom (schematic designator C40)
C40_A2 "1uF 25V" C0402 1545,2613.82 r0 bottom (schematic designator C40)
C40_A3 "1uF 25V" C0402 1547.52,1548.82 r0 bottom (schematic designator C40)
C40_A4 "1uF 25V" C0402 1547.52,1193.82 r0 bottom (schematic designator C40)
C41_A1 "0.1uF 50V" C0402 1911.87,3076.63 r90 bottom (schematic designator C41)
C41_A2 "0.1uF 50V" C0402 1911.87,2721.63 r90 bottom (schematic designator C41)
C41_A3 "0.1uF 50V" C0402 1914.39,1656.64 r90 bottom (schematic designator C41)
C41_A4 "0.1uF 50V" C0402 1914.39,1301.64 r90 bottom (schematic designator C41)
C42_A1 "0.1uF 50V" C0402 1851.87,3157.53 r0 bottom (schematic designator C42)
C42_A2 "0.1uF 50V" C0402 1851.87,2802.53 r0 bottom (schematic designator C42)
C42_A3 "0.1uF 50V" C0402 1854.39,1737.54 r0 bottom (schematic designator C42)
C42_A4 "0.1uF 50V" C0402 1854.39,1382.54 r0 bottom (schematic designator C42)
C43_A1 "10uF 10V" C0402 1851.87,3117.53 r0 bottom (schematic designator C43)
C43_A2 "10uF 10V" C0402 1851.87,2762.53 r0 bottom (schematic designator C43)
C43_A3 "10uF 10V" C0402 1854.39,1697.54 r0 bottom (schematic designator C43)
C43_A4 "10uF 10V" C0402 1854.39,1342.54 r0 bottom (schematic designator C43)
C44_B3 "1uF 25V" C0402 396.62,965.44 r0 top (schematic designator C44)
C44_B4 "1uF 25V" C0402 396.62,610.44 r0 top (schematic designator C44)
C45_B3 "1uF 25V" C0402 602.5,995.42 r0 top (schematic designator C45)
C45_B4 "1uF 25V" C0402 602.5,640.42 r0 top (schematic designator C45)
C46_B3 "16pF 50V" C0402 1154.35,965.42 r270 top (schematic designator C46)
C46_B4 "16pF 50V" C0402 1154.35,610.42 r270 top (schematic designator C46)
C47_B3 "11pF 50V" C0402 1069.35,961.32 r270 top (schematic designator C47)
C47_B4 "11pF 50V" C0402 1069.35,606.32 r270 top (schematic designator C47)
C48_B3 "10pF 50V" C0402 989.35,961.32 r270 top (schematic designator C48)
C48_B4 "10pF 50V" C0402 989.35,606.32 r270 top (schematic designator C48)
C49_B3 "13pF 50V" C0402 914.35,960.42 r270 top (schematic designator C49)
C49_B4 "13pF 50V" C0402 914.35,605.42 r270 top (schematic designator C49)
C50_B3 "1uF 25V" C0402 499.02,1010.01 r180 bottom (schematic designator C50)
C50_B4 "1uF 25V" C0402 499.02,655.01 r180 bottom (schematic designator C50)
C51_B3 "0.1uF 50V" C0402 498.42,1050.01 r180 bottom (schematic designator C51)
C51_B4 "0.1uF 50V" C0402 498.42,695.01 r180 bottom (schematic designator C51)
C52_B3 "0.1uF 50V" C0402 1567.52,898.82 r270 bottom (schematic designator C52)
C52_B4 "0.1uF 50V" C0402 1567.52,543.82 r270 bottom (schematic designator C52)
C53_B3 "1uF 25V" C0402 1547.52,838.82 r0 bottom (schematic designator C53)
C53_B4 "1uF 25V" C0402 1547.52,483.82 r0 bottom (schematic designator C53)
C54_B3 "0.1uF 50V" C0402 1914.39,946.64 r90 bottom (schematic designator C54)
C54_B4 "0.1uF 50V" C0402 1914.39,591.64 r90 bottom (schematic designator C54)
C55_B3 "0.1uF 50V" C0402 1854.39,1027.54 r0 bottom (schematic designator C55)
C55_B4 "0.1uF 50V" C0402 1854.39,672.54 r0 bottom (schematic designator C55)
C56_B3 "10uF 10V" C0402 1854.39,987.54 r0 bottom (schematic designator C56)
C56_B4 "10uF 10V" C0402 1854.39,632.54 r0 bottom (schematic designator C56)
F1 "PTC 24V / 1.5A" 1812_F 2465,587.44 r90 top
F2 "PTC 24V / 1.5A" 1812_F 2610,587.44 r90 top
F3 "PTC 24V / 1.5A" 1812_F 2320,587.44 r270 top
FB1_M1 "BLM18EG221SN1D" FB0603 2259.41,2497.52 r180 bottom (schematic designator FB1)
FB1_M2 "BLM18EG221SN1D" FB0603 2261.46,1069.11 r180 bottom (schematic designator FB1)
FB2 "BLM18EG221SN1D" FB0603 3219.76,1948.42 r180 top
FB3 "BLM18EG221SN1D" FB0603 2954.65,1793.42 r180 top
FB4 "BLM18EG221SN1D" FB0603 3220.41,1602.98 r180 top
FB5 "BLM18EG221SN1D" FB0603 2955.29,1447.98 r180 top
FID1 "Fiducial" FIDUCIAL 2860,3362.52 r90 top
FID2 "Fiducial" FIDUCIAL 3705,517.52 r90 top
FID3 "Fiducial" FIDUCIAL 435,292.52 r90 top
FID4 "Fiducial" FIDUCIAL 2865,3362.52 r90 bottom
FID5 "Fiducial" FIDUCIAL 3710,517.52 r90 bottom
FID6 "Fiducial" FIDUCIAL 445,292.52 r90 bottom
H1 "Hole 3mm" "HOLE 3MM" 3848.91,3090.92 r0 top
H2 "Hole 3mm" "HOLE 3MM" 187.5,3327.14 r0 top
H3 "Hole 3mm" "HOLE 3MM" 3848.91,590.92 r0 top
H4 "Hole 3mm" "HOLE 3MM" 187.5,315.33 r0 top
J1 "1053141204" CON_1053141204 3486.59,3347.53 r90 top
J2 "5767096-1" MICTOR-38_PIN 3477.4,2707.71 r90 top
J3 "90131-0770" HEADER_10X2 2654.39,3012.53 r270 top
J4 "90131-0770" HEADER_10X2 3234.39,3007.53 r270 top
J5 "90131-0770" HEADER_10X2 2949.39,3012.53 r270 top
J6 "10018784-10201TLF" PCIE_8LANE_EDGE 2810.18,256.72 r0 top locked
J7_A1 "SMA-J-P-H-RA-TH1" CONN_SMA-J-P-H-RA-TH1_SAI 180,3095 r90 top (schematic designator J7)
J7_A2 "SMA-J-P-H-RA-TH1" CONN_SMA-J-P-H-RA-TH1_SAI 180,2740 r90 top (schematic designator J7)
J7_A3 "SMA-J-P-H-RA-TH1" CONN_SMA-J-P-H-RA-TH1_SAI 182.52,1675.01 r90 top (schematic designator J7)
J7_A4 "SMA-J-P-H-RA-TH1" CONN_SMA-J-P-H-RA-TH1_SAI 182.52,1320.01 r90 top (schematic designator J7)
J8_A1 "MMCX-J-P-H-ST-TH1" SAMTEC_MMCX-J-P-H-ST-TH1 1490,3205 r270 top (schematic designator J8)
J8_A2 "MMCX-J-P-H-ST-TH1" SAMTEC_MMCX-J-P-H-ST-TH1 1490,2850 r270 top (schematic designator J8)
J8_A3 "MMCX-J-P-H-ST-TH1" SAMTEC_MMCX-J-P-H-ST-TH1 1492.52,1785.01 r270 top (schematic designator J8)
J8_A4 "MMCX-J-P-H-ST-TH1" SAMTEC_MMCX-J-P-H-ST-TH1 1492.52,1430.01 r270 top (schematic designator J8)
J9_B1 "SMA-J-P-H-RA-TH1" CONN_SMA-J-P-H-RA-TH1_SAI 6545.02,298.05 r90 top (schematic designator J9)
J9_B2 "SMA-J-P-H-RA-TH1" CONN_SMA-J-P-H-RA-TH1_SAI 6550.02,858.05 r90 top (schematic designator J9)
J9_B3 "SMA-J-P-H-RA-TH1" CONN_SMA-J-P-H-RA-TH1_SAI 182.52,965.01 r90 top (schematic designator J9)
J9_B4 "SMA-J-P-H-RA-TH1" CONN_SMA-J-P-H-RA-TH1_SAI 182.52,610.01 r90 top (schematic designator J9)
J10_B1 "MMCX-J-P-H-ST-TH1" SAMTEC_MMCX-J-P-H-ST-TH1 5325.02,413.05 r90 top (schematic designator J10)
J10_B2 "MMCX-J-P-H-ST-TH1" SAMTEC_MMCX-J-P-H-ST-TH1 5335.02,973.05 r90 top (schematic designator J10)
J10_B3 "MMCX-J-P-H-ST-TH1" SAMTEC_MMCX-J-P-H-ST-TH1 1492.52,1075.01 r270 top (schematic designator J10)
J10_B4 "MMCX-J-P-H-ST-TH1" SAMTEC_MMCX-J-P-H-ST-TH1 1492.52,720.01 r270 top (schematic designator J10)
L1_A1 "Inductor" 0402-A 1111.83,3145.41 r180 top value=56nH (schematic designator L1)
L1_A2 "Inductor" 0402-A 1111.83,2790.41 r180 top value=56nH (schematic designator L1)
L1_A3 "Inductor" 0402-A 1114.35,1725.42 r180 top value=56nH (schematic designator L1)
L1_A4 "Inductor" 0402-A 1114.35,1370.42 r180 top value=56nH (schematic designator L1)
L2_A1 "Inductor" 0402-A 1196.52,3145.41 r180 top value=43nH (schematic designator L2)
L2_A2 "Inductor" 0402-A 1196.52,2790.41 r180 top value=43nH (schematic designator L2)
L2_A3 "Inductor" 0402-A 1199.04,1725.42 r180 top value=43nH (schematic designator L2)
L2_A4 "Inductor" 0402-A 1199.04,1370.42 r180 top value=43nH (schematic designator L2)
L3_A1 "Inductor" 0402-A 1026.83,3145.41 r180 top value=43nH (schematic designator L3)
L3_A2 "Inductor" 0402-A 1026.83,2790.41 r180 top value=43nH (schematic designator L3)
L3_A3 "Inductor" 0402-A 1029.35,1725.42 r180 top value=43nH (schematic designator L3)
L3_A4 "Inductor" 0402-A 1029.35,1370.42 r180 top value=43nH (schematic designator L3)
L4_A1 "Inductor" 0402-A 946.83,3145.41 r180 top value=47nH (schematic designator L4)
L4_A2 "Inductor" 0402-A 946.83,2790.41 r180 top value=47nH (schematic designator L4)
L4_A3 "Inductor" 0402-A 949.35,1725.42 r180 top value=47nH (schematic designator L4)
L4_A4 "Inductor" 0402-A 949.35,1370.42 r180 top value=47nH (schematic designator L4)
L5_A1 "Inductor" 0402-A 861.83,3145.41 r180 top value=33nH (schematic designator L5)
L5_A2 "Inductor" 0402-A 861.83,2790.41 r180 top value=33nH (schematic designator L5)
L5_A3 "Inductor" 0402-A 864.35,1725.42 r180 top value=33nH (schematic designator L5)
L5_A4 "Inductor" 0402-A 864.35,1370.42 r180 top value=33nH (schematic designator L5)
L6_A1 "Inductor" 0402-A 1066.83,3005.73 r270 top value=24nH (schematic designator L6)
L6_A2 "Inductor" 0402-A 1066.83,2650.73 r270 top value=24nH (schematic designator L6)
L6_A3 "Inductor" 0402-A 1069.35,1585.74 r270 top value=24nH (schematic designator L6)
L6_A4 "Inductor" 0402-A 1069.35,1230.74 r270 top value=24nH (schematic designator L6)
L7_A1 "Inductor" 0402-A 986.83,3005.73 r270 top value=33nH (schematic designator L7)
L7_A2 "Inductor" 0402-A 986.83,2650.73 r270 top value=33nH (schematic designator L7)
L7_A3 "Inductor" 0402-A 989.35,1585.74 r270 top value=33nH (schematic designator L7)
L7_A4 "Inductor" 0402-A 989.35,1230.74 r270 top value=33nH (schematic designator L7)
L8_A1 "Inductor" 0402-A 911.83,3000.41 r270 top value=15nH (schematic designator L8)
L8_A2 "Inductor" 0402-A 911.83,2645.41 r270 top value=15nH (schematic designator L8)
L8_A3 "Inductor" 0402-A 914.35,1580.42 r270 top value=15nH (schematic designator L8)
L8_A4 "Inductor" 0402-A 914.35,1225.42 r270 top value=15nH (schematic designator L8)
L9_A1 "Inductor" 0402-A 1151.83,3005.73 r270 top value=3.9nH (schematic designator L9)
L9_A2 "Inductor" 0402-A 1151.83,2650.73 r270 top value=3.9nH (schematic designator L9)
L9_A3 "Inductor" 0402-A 1154.35,1585.74 r270 top value=3.9nH (schematic designator L9)
L9_A4 "Inductor" 0402-A 1154.35,1230.74 r270 top value=3.9nH (schematic designator L9)
L10_B1 "Inductor" 0402-A 4835.02,458.05 r90 top value=56nH (schematic designator L10)
L10_B2 "Inductor" 0402-A 4840.02,1018.05 r90 top value=56nH (schematic designator L10)
L10_B3 "Inductor" 0402-A 1114.35,1015.42 r180 top value=56nH (schematic designator L10)
L10_B4 "Inductor" 0402-A 1114.35,660.42 r180 top value=56nH (schematic designator L10)
L11_B1 "Inductor" 0402-A 4680.02,458.05 r90 top value=43nH (schematic designator L11)
L11_B2 "Inductor" 0402-A 4685.02,1018.05 r90 top value=43nH (schematic designator L11)
L11_B3 "Inductor" 0402-A 1199.04,1015.42 r180 top value=43nH (schematic designator L11)
L11_B4 "Inductor" 0402-A 1199.04,660.42 r180 top value=43nH (schematic designator L11)
L12_B1 "Inductor" 0402-A 4755.02,458.05 r90 top value=43nH (schematic designator L12)
L12_B2 "Inductor" 0402-A 4760.02,1018.05 r90 top value=43nH (schematic designator L12)
L12_B3 "Inductor" 0402-A 1029.35,1015.42 r180 top value=43nH (schematic designator L12)
L12_B4 "Inductor" 0402-A 1029.35,660.42 r180 top value=43nH (schematic designator L12)
L13_B1 "Inductor" 0402-A 4375.02,458.05 r90 top value=47nH (schematic designator L13)
L13_B2 "Inductor" 0402-A 4375.02,1018.05 r90 top value=47nH (schematic designator L13)
L13_B3 "Inductor" 0402-A 949.35,1015.42 r180 top value=47nH (schematic designator L13)
L13_B4 "Inductor" 0402-A 949.35,660.42 r180 top value=47nH (schematic designator L13)
L14_B1 "Inductor" 0402-A 4450.02,458.05 r90 top value=33nH (schematic designator L14)
L14_B2 "Inductor" 0402-A 4450.02,1018.05 r90 top value=33nH (schematic designator L14)
L14_B3 "Inductor" 0402-A 864.35,1015.42 r180 top value=33nH (schematic designator L14)
L14_B4 "Inductor" 0402-A 864.35,660.42 r180 top value=33nH (schematic designator L14)
L15_B1 "Inductor" 0402-A 4065.02,458.05 r90 top value=3.9nH (schematic designator L15)
L15_B2 "Inductor" 0402-A 4065.02,1018.05 r90 top value=3.9nH (schematic designator L15)
L15_B3 "Inductor" 0402-A 1154.35,875.74 r270 top value=3.9nH (schematic designator L15)
L15_B4 "Inductor" 0402-A 1154.35,520.74 r270 top value=3.9nH (schematic designator L15)
L16_B1 "Inductor" 0402-A 4140.02,458.05 r90 top value=24nH (schematic designator L16)
L16_B2 "Inductor" 0402-A 4140.02,1018.05 r90 top value=24nH (schematic designator L16)
L16_B3 "Inductor" 0402-A 1069.35,875.74 r270 top value=24nH (schematic designator L16)
L16_B4 "Inductor" 0402-A 1069.35,520.74 r270 top value=24nH (schematic designator L16)
L17_B1 "Inductor" 0402-A 4220.02,458.05 r90 top value=33nH (schematic designator L17)
L17_B2 "Inductor" 0402-A 4220.02,1018.05 r90 top value=33nH (schematic designator L17)
L17_B3 "Inductor" 0402-A 989.35,875.74 r270 top value=33nH (schematic designator L17)
L17_B4 "Inductor" 0402-A 989.35,520.74 r270 top value=33nH (schematic designator L17)
L18_B1 "Inductor" 0402-A 4295.02,458.05 r90 top value=15nH (schematic designator L18)
L18_B2 "Inductor" 0402-A 4295.02,1018.05 r90 top value=15nH (schematic designator L18)
L18_B3 "Inductor" 0402-A 914.35,870.42 r270 top value=15nH (schematic designator L18)
L18_B4 "Inductor" 0402-A 914.35,515.42 r270 top value=15nH (schematic designator L18)
LD1 "APT1608SGC" LED_0603_GREEN 2759.37,1875.5 r90 top
LD2 "APT1608SGC" LED_0603_GREEN 2760.02,1530.06 r90 top
Lp1 "NR6028T100M" IND6X6_H3 3544.65,1662.52 r180 top
R1_M1 "6.8K" R0402 2361.85,2547.52 r0 bottom (schematic designator R1)
R1_M2 "6.8K" R0402 2363.9,1119.11 r0 bottom (schematic designator R1)
R2_M1 "0R" R0402 2366.85,2752.52 r180 bottom (schematic designator R2)
R2_M2 "0R" R0402 2368.9,1324.11 r180 bottom (schematic designator R2)
R3_M1 "10K" R0402 3317.89,752.33 r270 top (schematic designator R3)
R3_M2 "10K" R0402 3112.89,757.33 r270 top (schematic designator R3)
R4_M1 "10K" R0402 3357.89,752.33 r270 top (schematic designator R4)
R4_M2 "10K" R0402 3152.89,757.33 r270 top (schematic designator R4)
R5_M1 "10K" R0402 3397.89,752.33 r270 top (schematic designator R5)
R5_M2 "10K" R0402 3192.89,757.33 r270 top (schematic designator R5)
R6_M1 "10K" R0402 3437.89,752.33 r270 top (schematic designator R6)
R6_M2 "10K" R0402 3232.89,757.33 r270 top (schematic designator R6)
R7_M1 "NA" R0402 2088.35,2492.52 r180 bottom (schematic designator R7)
R7_M2 "NA" R0402 2090.4,1064.11 r180 bottom (schematic designator R7)
R8_M1 "0R" R0402 2386.85,2614.02 r270 bottom (schematic designator R8)
R8_M2 "0R" R0402 2388.9,1185.61 r270 bottom (schematic designator R8)
R9_M1 "0R" R0402 2146.85,2513.42 r270 bottom (schematic designator R9)
R9_M2 "0R" R0402 2148.9,1085.01 r270 bottom (schematic designator R9)
R10_M1 "NA" R0402 2365.35,2672.52 r0 bottom (schematic designator R10)
R10_M2 "NA" R0402 2367.4,1244.11 r0 bottom (schematic designator R10)
R11_M1 "10K" R0402 2206.85,2762.52 r90 bottom (schematic designator R11)
R11_M2 "10K" R0402 2208.9,1334.11 r90 bottom (schematic designator R11)
R12_M1 "10K" R0402 2166.85,2762.52 r90 bottom (schematic designator R12)
R12_M2 "10K" R0402 2168.9,1334.11 r90 bottom (schematic designator R12)
R13_M1 "10K" R0402 2126.85,2762.52 r90 bottom (schematic designator R13)
R13_M2 "10K" R0402 2128.9,1334.11 r90 bottom (schematic designator R13)
R14_M1 "10K" R0402 2086.85,2762.52 r90 bottom (schematic designator R14)
R14_M2 "10K" R0402 2088.9,1334.11 r90 bottom (schematic designator R14)
R15_M1 "0R" R0805 2061.87,2187.53 r180 bottom (schematic designator R15)
R15_M2 "0R" R0805 2064.39,731.27 r180 bottom (schematic designator R15)
R16_M1 "0R" R0805 2061.87,2267.53 r180 bottom (schematic designator R16)
R16_M2 "0R" R0805 2064.39,811.27 r180 bottom (schematic designator R16)
R17_M1 "0R" R0805 2071.87,2862.53 r180 bottom (schematic designator R17)
R17_M2 "0R" R0805 2074.39,1406.27 r180 bottom (schematic designator R17)
R18_M1 "0R" R0805 2071.87,3247.53 r180 bottom (schematic designator R18)
R18_M2 "0R" R0805 2074.39,1791.27 r180 bottom (schematic designator R18)
R19_M1 "0R" R0805 2061.87,2047.53 r180 bottom (schematic designator R19)
R19_M2 "0R" R0805 2064.39,591.27 r180 bottom (schematic designator R19)
R20_M1 "0R" R0805 2061.87,2337.53 r180 bottom (schematic designator R20)
R20_M2 "0R" R0805 2064.39,881.27 r180 bottom (schematic designator R20)
R21_M1 "0R" R0805 2071.87,3002.53 r180 bottom (schematic designator R21)
R21_M2 "0R" R0805 2074.39,1546.27 r180 bottom (schematic designator R21)
R22_M1 "0R" R0805 2071.87,3177.53 r180 bottom (schematic designator R22)
R22_M2 "0R" R0805 2074.39,1721.27 r180 bottom (schematic designator R22)
R23_M1 "0R" R0805 2061.87,2117.53 r180 bottom (schematic designator R23)
R23_M2 "0R" R0805 2064.39,661.27 r180 bottom (schematic designator R23)
R24_M1 "0R" R0805 2061.87,2402.53 r180 bottom (schematic designator R24)
R24_M2 "0R" R0805 2064.39,946.27 r180 bottom (schematic designator R24)
R25_M1 "0R" R0805 2071.87,2932.53 r180 bottom (schematic designator R25)
R25_M2 "0R" R0805 2074.39,1476.27 r180 bottom (schematic designator R25)
R26_M1 "0R" R0805 2071.87,3107.53 r180 bottom (schematic designator R26)
R26_M2 "0R" R0805 2074.39,1651.27 r180 bottom (schematic designator R26)
R27 "124K" R0402 3087.2,1714.32 r270 top
R28 "1K" R0402 2757.2,1784.92 r270 top
R29 "39.2K" R0402 3127.2,1712.52 r90 top
R30 "124K" R0402 3087.85,1368.88 r270 top
R31 "1K" R0402 2757.85,1439.48 r270 top
R32 "100K" R0402 3127.85,1367.08 r90 top
R33 "0R" R0402 2305,1938.5 r90 top
R34_LS1 "100K" R0402 2907.89,656.43 r270 top (schematic designator R34)
R34_LS2 "100K" R0402 2737.89,651.43 r90 top (schematic designator R34)
R34_LS3 "100K" R0402 3292.89,656.43 r90 top (schematic designator R34)
R34_LS4 "100K" R0402 3087.89,651.43 r90 top (schematic designator R34)
R35_LS1 "NA" R0402 2907.89,571.43 r90 top (schematic designator R35)
R35_LS2 "NA" R0402 2737.89,564.93 r90 top (schematic designator R35)
R35_LS3 "NA" R0402 3292.89,570.53 r90 top (schematic designator R35)
R35_LS4 "NA" R0402 3087.89,566.43 r90 top (schematic designator R35)
R36_A1 "34.8R" R0402 675.88,3145.41 r180 top (schematic designator R36)
R36_A2 "34.8R" R0402 675.88,2790.41 r180 top (schematic designator R36)
R36_A3 "34.8R" R0402 678.4,1725.42 r180 top (schematic designator R36)
R36_A4 "34.8R" R0402 678.4,1370.42 r180 top (schematic designator R36)
R37_A1 "34.8R" R0402 787.51,3145.43 r180 top (schematic designator R37)
R37_A2 "34.8R" R0402 787.51,2790.43 r180 top (schematic designator R37)
R37_A3 "34.8R" R0402 790.03,1725.44 r180 top (schematic designator R37)
R37_A4 "34.8R" R0402 790.03,1370.44 r180 top (schematic designator R37)
R38_A1 "18.2R" R0402 729.98,3126.91 r270 top (schematic designator R38)
R38_A2 "18.2R" R0402 729.98,2771.91 r270 top (schematic designator R38)
R38_A3 "18.2R" R0402 732.5,1706.92 r270 top (schematic designator R38)
R38_A4 "18.2R" R0402 732.5,1351.92 r270 top (schematic designator R38)
R39_A1 "49.9R" R0402 1911.87,3076.03 r90 top (schematic designator R39)
R39_A2 "49.9R" R0402 1911.87,2721.03 r90 top (schematic designator R39)
R39_A3 "49.9R" R0402 1914.39,1656.04 r90 top (schematic designator R39)
R39_A4 "49.9R" R0402 1914.39,1301.04 r90 top (schematic designator R39)
R40_A1 "49.9R" R0402 1911.87,3236.03 r90 top (schematic designator R40)
R40_A2 "49.9R" R0402 1911.87,2881.03 r90 top (schematic designator R40)
R40_A3 "49.9R" R0402 1914.39,1816.04 r90 top (schematic designator R40)
R40_A4 "49.9R" R0402 1914.39,1461.04 r90 top (schematic designator R40)
R41_A1 "NA" R0402 1283.5,3165 r0 top (schematic designator R41)
R41_A2 "NA" R0402 1283.5,2810 r0 top (schematic designator R41)
R41_A3 "NA" R0402 1286.02,1745.01 r0 top (schematic designator R41)
R41_A4 "NA" R0402 1286.02,1390.01 r0 top (schematic designator R41)
R42_A1 "0R" R0402 1285.9,3125 r180 top (schematic designator R42)
R42_A2 "0R" R0402 1285.9,2770 r180 top (schematic designator R42)
R42_A3 "0R" R0402 1288.42,1705.01 r180 top (schematic designator R42)
R42_A4 "0R" R0402 1288.42,1350.01 r180 top (schematic designator R42)
R43_B1 "34.8R" r0402 5915.02,453.05 r90 top (schematic designator R43)
R43_B2 "34.8R" r0402 5925.02,1013.05 r90 top (schematic designator R43)
R43_B3 "34.8R" R0402 678.4,1015.42 r180 top (schematic designator R43)
R43_B4 "34.8R" R0402 678.4,660.42 r180 top (schematic designator R43)
R44_B1 "34.8R" r0402 6005.02,453.05 r90 top (schematic designator R44)
R44_B2 "34.8R" r0402 6015.02,1013.05 r90 top (schematic designator R44)
R44_B3 "34.8R" R0402 790.03,1015.44 r180 top (schematic designator R44)
R44_B4 "34.8R" R0402 790.03,660.44 r180 top (schematic designator R44)
R45_B1 "18.2R" r0402 5825.02,453.05 r90 top (schematic designator R45)
R45_B2 "18.2R" r0402 5835.02,1013.05 r90 top (schematic designator R45)
R45_B3 "18.2R" R0402 732.5,996.92 r270 top (schematic designator R45)
R45_B4 "18.2R" R0402 732.5,641.92 r270 top (schematic designator R45)
R46_B3 "49.9R" R0402 1912.52,1105.01 r270 top (schematic designator R46)
R46_B4 "49.9R" R0402 1912.52,750.91 r270 top (schematic designator R46)
R47_B3 "49.9R" R0402 1914.39,946.04 r270 top (schematic designator R47)
R47_B4 "49.9R" R0402 1917.52,590.01 r270 top (schematic designator R47)
R48_B1 "NA" r0402 4950.02,473.05 r0 top (schematic designator R48)
R48_B2 "NA" r0402 4955.02,1033.05 r0 top (schematic designator R48)
R48_B3 "NA" R0402 1286.02,1035.01 r0 top (schematic designator R48)
R48_B4 "NA" R0402 1286.02,680.01 r0 top (schematic designator R48)
R49_B1 "0R" r0402 4565.02,473.05 r0 top (schematic designator R49)
R49_B2 "0R" r0402 4570.02,1033.05 r0 top (schematic designator R49)
R49_B3 "0R" R0402 1288.42,995.01 r180 top (schematic designator R49)
R49_B4 "0R" R0402 1288.42,640.01 r180 top (schematic designator R49)
SH1_M1 "RF_SHIELD" SMS201F 2238.9,1214.11 r0 top (schematic designator SH1)
SH1_M2 "RF_SHIELD" SMS201F 2236.85,2642.52 r0 top (schematic designator SH1)
T1_A1 "ADTT1-1+" CD542_MNC 1739.82,3156.23 r180 top (schematic designator T1)
T1_A2 "ADTT1-1+" CD542_MNC 1739.82,2801.23 r180 top (schematic designator T1)
T1_A3 "ADTT1-1+" CD542_MNC 1742.34,1736.24 r180 top (schematic designator T1)
T1_A4 "ADTT1-1+" CD542_MNC 1742.34,1381.24 r180 top (schematic designator T1)
T2_B1 "ADTT1-1+" CD542_MNC 5605.02,328.05 r0 top (schematic designator T2)
T2_B2 "ADTT1-1+" CD542_MNC 5588.91,940 r180 top (schematic designator T2)
T2_B3 "ADTT1-1+" CD542_MNC 1742.34,1026.24 r180 top (schematic designator T2)
T2_B4 "ADTT1-1+" CD542_MNC 1742.34,671.24 r180 top (schematic designator T2)
TP1 "+12V" TP_2X1.8 3425,1432.52 r270 top
TP2 "+3.3V" TP_2X1.8 2847.2,1793.42 r90 top
TP3 "+1.8V" TP_2X1.8 2847.85,1447.98 r90 top
TP4 "SyncIn" TP_2X1.8 2455,2287.52 r90 top
TP5 "SyncOut" TP_2X1.8 2460,842.52 r270 top
TP6 "GND" TP_2X1.8 3860,2892.52 r270 top
TP7 "GND" TP_2X1.8 3855,747.52 r0 top
U1_M1 "AD9959BCPZ" CP_56_1_ADI 2236.85,2642.52 r90 top (schematic designator U1)
U1_M2 "AD9959BCPZ" CP_56_1_ADI 2238.9,1214.11 r90 top (schematic designator U1)
U2 "MUN12AD03-SEC" SO8_MUN12AD_DEA 3095,1832.52 r270 top
U3 "MUN12AD03-SEC" SO8_MUN12AD_DEA 3095.65,1487.08 r270 top
U4_LS1 "74AVC4T774_GU" NXP_74AVC4T245GU,115 2999.27,599.82 r90 top (schematic designator U4)
U4_LS2 "74AVC4T774_GU" NXP_74AVC4T245GU,115 2822.89,599.82 r90 top (schematic designator U4)
U4_LS3 "74AVC4T774_GU" NXP_74AVC4T245GU,115 3377.89,599.82 r90 top (schematic designator U4)
U4_LS4 "74AVC4T774_GU" NXP_74AVC4T245GU,115 3177.89,599.82 r90 top (schematic designator U4)
U5_A1 "BGA2815,115" SOT_2815,115_NXP 498.11,3120.43 r0 top (schematic designator U5)
U5_A2 "BGA2815,115" SOT_2815,115_NXP 498.11,2765.43 r0 top (schematic designator U5)
U5_A3 "BGA2815,115" SOT_2815,115_NXP 500.63,1700.44 r0 top (schematic designator U5)
U5_A4 "BGA2815,115" SOT_2815,115_NXP 500.63,1345.44 r0 top (schematic designator U5)
U6_A1 "ADG901BCPZ-500RL7" CP_8_2_ADI 1505,3027.52 r180 top (schematic designator U6)
U6_A2 "ADG901BCPZ-500RL7" CP_8_2_ADI 1505,2672.52 r180 top (schematic designator U6)
U6_A3 "ADG901BCPZ-500RL7" CP_8_2_ADI 1507.52,1607.53 r180 top (schematic designator U6)
U6_A4 "ADG901BCPZ-500RL7" CP_8_2_ADI 1507.52,1252.53 r180 top (schematic designator U6)
U7_B1 "BGA2815,115" SOT_2815,115_NXP 6790.02,433.05 r90 top (schematic designator U7)
U7_B2 "BGA2815,115" SOT_2815,115_NXP 6800.02,993.05 r90 top (schematic designator U7)
U7_B3 "BGA2815,115" SOT_2815,115_NXP 500.63,990.44 r0 top (schematic designator U7)
U7_B4 "BGA2815,115" SOT_2815,115_NXP 500.63,635.44 r0 top (schematic designator U7)
U8_B1 "ADG901BCPZ-500RL7" CP_8_2_ADI 5125.02,413.05 r90 top (schematic designator U8)
U8_B2 "ADG901BCPZ-500RL7" CP_8_2_ADI 5135.02,973.05 r90 top (schematic designator U8)
U8_B3 "ADG901BCPZ-500RL7" CP_8_2_ADI 1507.52,897.53 r180 top (schematic designator U8)
U8_B4 "ADG901BCPZ-500RL7" CP_8_2_ADI 1507.52,542.53 r180 top (schematic designator U8)
Y1_M1 "ECS-250-20-33-CKM-TR3" SMD4_ECX-32_3P2X2P5_ECS 2500.4,2597.24 r0 bottom (schematic designator Y1)
Y1_M2 "ECS-250-20-33-CKM-TR3" SMD4_ECX-32_3P2X2P5_ECS 2529.75,1216 r0 bottom (schematic designator Y1)

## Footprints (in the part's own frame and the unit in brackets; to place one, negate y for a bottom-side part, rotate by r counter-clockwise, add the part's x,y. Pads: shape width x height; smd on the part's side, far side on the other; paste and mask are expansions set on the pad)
0402-A [mm] "Chip Inductor, Body 1.0x0.5mm, IPC High Density"
  rect 0.6x0.5 smd mask+0.051: 1(-0.5,0) 2(0.5,0)
  silkscreen extent -1.1,-0.15 -1.1,0.15, body extent -0.55,-0.3 0.55,0.3, height 0.55
1812_F [mm] "PTC RESETTABLE 33V 1.10A 1812L"
  rect 1.78x3.15 smd mask+0.051: 1(-2.665,0) 2(2.665,0)
  silkscreen extent -2.4,-1.7 2.4,1.7, body extent -2.36,-1.74 2.37,1.74, height 1.03
C0402 [mil]
  rect 25x25 smd mask+2: 1(-18.5,0) 2(20.9,0)
  silkscreen extent -36,-17 40,17, body extent -20,-12 20,12, height 8
C0603 [mm]
  rect 0.7x0.9 smd mask+0.051: 1(-0.7,0) 2(0.7,0)
  silkscreen extent -1.2,-0.6 1.2,0.6, body extent -0.8,-0.4 0.8,0.4, height 0.3
CD542_MNC [mil]
  rect 37.81x28.03 smd paste+0 mask+2: 1(-128.91,100) 2(-128.91,0) 3(-128.91,-100) 4(128.91,-100) 5(128.91,0) 6(128.91,100)
  silkscreen extent -115,-160 115,160, body extent -136,-155 136,155, height 112
CON_1053141204 [mm]
  rect 1.7x1.7 hole 1.2 mask+0.076: 1(0,0)
  round 1.7 hole 1.2 mask+0.076: 2(-2.5,0) 3(0,-2.5) 4(-2.5,-2.5)
  round 1.6 hole 1.6 unplated mask+0.076: 5(0,-9.68) 6(-2.5,-9.68)
  silkscreen extent -4.22,-12.88 3.5,0.64, body extent -4.24,-14.2 1.7,0.46, height 8.85
CONN_SMA-J-P-H-RA-TH1_SAI [mil]
  round 83 hole 63 mask+0: 1(0,0) 2(-100,100) 3(-100,-100) 4(100,-100) 5(100,100)
  silkscreen extent -143,-143 191,466, body extent -136,-137 140,457, height 372
CP_8_2_ADI [mm]
  rect 0.808x0.255 smd paste+0 mask+0.051: 1(-1.522,0.75) 2(-1.522,0.25) 3(-1.522,-0.25) 4(-1.522,-0.75) 5(1.522,-0.75) 6(1.522,-0.25) 7(1.522,0.25) 8(1.522,0.75)
  rect 1.6x1.88 smd paste+0 mask+0.051: 9(0,0)
  silkscreen extent -1.75,-1.75 1.75,1.75, body extent -1.63,-1.63 1.63,1.63, height 0.84
CP_56_1_ADI [mm]
  rect 0.808x0.255 smd paste+0 mask+0.051: 1(-3.896,3.25) 2(-3.896,2.75) 3(-3.896,2.25) 4(-3.896,1.75) 5(-3.896,1.25) 6(-3.896,0.75) 7(-3.896,0.25) 8(-3.896,-0.25) 9(-3.896,-0.75) 10(-3.896,-1.25) 11(-3.896,-1.75) 12(-3.896,-2.25) 13(-3.896,-2.75) 14(-3.896,-3.25) 29(3.896,-3.25) 30(3.896,-2.75) 31(3.896,-2.25) 32(3.896,-1.75) 33(3.896,-1.25) 34(3.896,-0.75) 35(3.896,-0.25) 36(3.896,0.25) 37(3.896,0.75) 38(3.896,1.25) 39(3.896,1.75) 40(3.896,2.25) 41(3.896,2.75) 42(3.896,3.25)
  rect 0.255x0.808 smd paste+0 mask+0.051: 15(-3.25,-3.896) 16(-2.75,-3.896) 17(-2.25,-3.896) 18(-1.75,-3.896) 19(-1.25,-3.896) 20(-0.75,-3.896) 21(-0.25,-3.896) 22(0.25,-3.896) 23(0.75,-3.896) 24(1.25,-3.896) 25(1.75,-3.896) 26(2.25,-3.896) 27(2.75,-3.896) 28(3.25,-3.896) 43(3.25,3.896) 44(2.75,3.896) 45(2.25,3.896) 46(1.75,3.896) 47(1.25,3.896) 48(0.75,3.896) 49(0.25,3.896) 50(-0.25,3.896) 51(-0.75,3.896) 52(-1.25,3.896) 53(-1.75,3.896) 54(-2.25,3.896) 55(-2.75,3.896) 56(-3.25,3.896)
  rect 6.248x6.248 smd paste-3.111 mask+0.051: 57(0,0)
  silkscreen extent -4.13,-4.13 4.13,4.13, body extent -4,-4 4,4, height 0.99
FB0603 [mm]
  rect 0.7x0.9 smd mask+0.051: 1(-0.7,0) 2(0.7,0)
  silkscreen extent -1.2,-0.6 1.2,0.6, body extent -0.76,-0.38 0.76,0.38, height 0.8
FIDUCIAL [mil]
  round 40 smd mask+20: 1(0,0)
  TOP_L1 pour cut-out: 43.31,0 43.31,4.27 41.64,12.63 38.38,20.51 33.64,27.61 27.61,33.64 20.51,38.38 12.63,41.64 4.27,43.31 0,43.31 -4.27,43.31 -12.63,41.64 -20.51,38.38 -27.61,33.64 -33.64,27.61 -38.38,20.51 -41.64,12.63 -43.31,4.27 -43.31,0 -43.31,-4.27 -41.64,-12.63 -38.38,-20.51 -33.64,-27.61 -27.61,-33.64 -20.51,-38.38 -12.63,-41.64 -4.27,-43.31 0,-43.31 4.27,-43.31 12.63,-41.64 20.51,-38.38 27.61,-33.64 33.64,-27.61 38.38,-20.51 41.64,-12.63 43.31,-4.27 43.31,0
HEADER_10X2 [mm]
  rect 1.7x1.7 hole 1.1 mask+0.05: 1(0,0)
  round 1.7 hole 1.1 mask+0.05: 2(0,2.54) 3(2.54,0) 4(2.54,2.54) 5(5.08,0) 6(5.08,2.54) 7(7.62,0) 8(7.62,2.54) 9(10.16,0) 10(10.16,2.54) 11(12.7,0) 12(12.7,2.54) 13(15.24,0) 14(15.24,2.54) 15(17.78,0) 16(17.78,2.54) 17(20.32,0) 18(20.32,2.54) 19(22.86,0) 20(22.86,2.54)
  silkscreen extent -1.27,-1.17 24.13,3.71, body extent -1.27,-1.27 24.13,3.81, height 7.75
"HOLE 3MM" [mm] "hole 3mm"
  round 4 hole 3.2: 1(0,0)
IND6X6_H3 [mm]
  rect 2.3x6.6 smd mask+0.051: 1(-2.15,0) 2(2.15,0)
  silkscreen extent -3.5,-3.56 3.5,3.5, body extent -3.1,-3.1 3.1,3.1, height 3.5
LED_0603_GREEN [mm] "LED 0603, Green"
  rect 0.7x0.9 smd mask+0.051: 1(-0.7,0) 2(0.7,0)
  silkscreen extent -1.14,-0.6 1.52,0.6, body extent -0.8,-0.4 0.8,0.4, height 0.7
MICTOR-38_PIN [mm]
  round 1.524 hole 2.43: 0(5.71,-3.495)
  rrect50% 0.43x1.6 smd mask+0.051: 1(0,0) 2(0,-6.99) 3(-0.635,0) 4(-0.635,-6.99) 5(-1.27,0) 6(-1.27,-6.99) 7(-1.905,0) 8(-1.905,-6.99) 9(-2.54,0) 10(-2.54,-6.99) 11(-3.175,0) 12(-3.175,-6.99) 13(-3.81,0) 14(-3.81,-6.99) 15(-4.445,0) 16(-4.445,-6.99) 17(-5.08,0) 18(-5.08,-6.99) 19(-5.715,0) 20(-5.715,-6.99) 21(-6.35,0) 22(-6.35,-6.99) 23(-6.985,0) 24(-6.985,-6.99) 25(-7.62,0) 26(-7.62,-6.99) 27(-8.255,0) 28(-8.255,-6.99) 29(-8.89,0) 30(-8.89,-6.99) 31(-9.525,0) 32(-9.525,-6.99) 33(-10.16,0) 34(-10.16,-6.99) 35(-10.795,0) 36(-10.795,-6.99) 37(-11.43,0) 38(-11.43,-6.99)
  round 1.2 hole 0.86: 39(-0.64,-3.495) 40(-3.18,-3.495) 41(-5.72,-3.495) 42(-8.26,-3.495) 43(-10.8,-3.495)
  silkscreen extent -18.8,-6.99 7.3,0, body extent -18.42,-7.85 6.98,0.86, height 6.05
NXP_74AVC4T245GU,115 [mm]
  rect 0.65x0.22 smd mask+0.051: 1(-0.725,0.6)
  rect 0.55x0.22 smd mask+0.051: 2(-0.775,0.2) 3(-0.775,-0.2) 4(-0.775,-0.6) 9(0.775,-0.6) 10(0.775,-0.2) 11(0.775,0.2) 12(0.775,0.6)
  rect 0.22x0.55 smd mask+0.051: 5(-0.6,-1.175) 6(-0.2,-1.175) 7(0.2,-1.175) 8(0.6,-1.175) 13(0.6,1.175) 14(0.2,1.175) 15(-0.2,1.175) 16(-0.6,1.175)
  silkscreen extent -1.05,-1.45 1.05,1.45, body extent -0.9,-1.3 0.9,1.3, height 0.5
PCIE_8LANE_EDGE [mil] "PCIE_8LANE_EDGE"
  rect 28x126 smd far side paste-100: A1(-984.25,-93.98)
  rect 28x169 smd far side paste-100: A2(-944.88,-115.48) A3(-905.51,-115.48) A4(-866.14,-115.48) A5(-826.77,-115.48) A6(-787.4,-115.48) A7(-748.03,-115.48) A8(-708.66,-115.48) A9(-669.29,-115.48) A10(-629.92,-115.48) A11(-590.55,-115.48) A12(-472.44,-115.48) A13(-433.07,-115.48) A14(-393.7,-115.48) A15(-354.33,-115.48) A16(-314.96,-115.48) A17(-275.59,-115.48) A18(-236.22,-115.48) A19(-196.85,-115.48) A20(-157.48,-115.48) A21(-118.11,-115.48) A22(-78.74,-115.48) A23(-39.37,-115.48) A24(0,-115.48) A25(39.37,-115.48) A26(78.74,-115.48) A27(118.11,-115.48) A28(157.48,-115.48) A29(196.85,-115.48) A30(236.22,-115.48) A31(275.59,-115.48) A32(314.96,-115.48)
  rect 28x169 smd paste-100 mask+2: B1(-984.25,-115.48) B2(-944.88,-115.48) B3(-905.51,-115.48) B4(-866.14,-115.48) B5(-826.77,-115.48) B6(-787.4,-115.48) B7(-748.03,-115.48) B8(-708.66,-115.48) B9(-669.29,-115.48) B10(-629.92,-115.48) B11(-590.55,-115.48) B12(-472.44,-115.48) B13(-433.07,-115.48) B14(-393.7,-115.48) B15(-354.33,-115.48) B16(-314.96,-115.48) B18(-236.22,-115.48) B19(-196.85,-115.48) B20(-157.48,-115.48) B21(-118.11,-115.48) B22(-78.74,-115.48) B23(-39.37,-115.48) B24(0,-115.48) B25(39.37,-115.48) B26(78.74,-115.48) B27(118.11,-115.48) B28(157.48,-115.48) B29(196.85,-115.48) B30(236.22,-115.48) B32(314.96,-115.48)
  rect 28x126 smd paste-100 mask+2: B17(-275.59,-93.98) B31(275.59,-93.98)
R0402 [mil] "R0402"
  rect 25x25 smd mask+2: 1(-18.5,0) 2(20.9,0)
  silkscreen extent -36,-17 40,17, body extent -20,-10 20,10, height 14
r0402 [mil] "R0402"
  rect 25x25 smd mask+2: 1(-18.5,0) 2(20.9,0)
  silkscreen extent -36,-17 40,17, body extent -20,-10 20,10, height 14
R0805 [mil] "R0805"
  rect 60x50 smd mask+2: 1(-45,0) 2(45,0)
  silkscreen extent -80,-30 80,30, body extent -39,-25 39,24, height 31
SAMTEC_MMCX-J-P-H-ST-TH1 [mm]
  round 1.348 hole 0.84: 1(0,0) S1(-1.27,1.27) S2(1.27,1.27) S3(1.27,-1.27) S4(-1.27,-1.27)
  silkscreen extent -1.75,-1.75 1.75,1.75, body extent -1.75,-1.75 1.75,1.75, height 4.35
SMD4_ECX-32_3P2X2P5_ECS [mm]
  rect 1.1x1.3 smd paste-0.55 mask+0.051: 1(-0.9,1.15) 2(-0.9,-1.15) 3(0.9,-1.15) 4(0.9,1.15)
  silkscreen extent -1.42,-0.17 1.42,0.17, body extent -1.3,-1.65 1.3,1.65, height 0.81
SMS201F [mm]
  rect 1x3.12 smd mask+0.051: 1(-6.3,-5.695) 1(6.3,-5.695)
  rect 1x3.79 smd mask+0.051: 1(-6.3,-0.03) 1(6.3,-0.03)
  rect 1x3.18 smd mask+0.051: 1(-6.3,5.665) 1(6.3,5.665)
  rect 1.75x1 smd mask+0.051: 1(-4.925,-6.755) 1(-4.925,6.755)
  rect 3.81x1 smd mask+0.051: 1(0.045,-6.755) 1(0.045,6.755)
  rect 1.64x1 smd mask+0.051: 1(4.98,-6.755) 1(4.98,6.755)
  silkscreen extent -6.35,-6.84 6.35,6.84, body extent -6.7,-7.15 6.7,7.15, height 2.64
SO8_MUN12AD_DEA [mm]
  rect 0.91x0.458 smd paste+0 mask+0.051: 1(-1.293,0.975) 2(-1.293,0.325) 3(-1.293,-0.325) 4(-1.293,-0.975) 5(1.293,-0.975) 6(1.293,-0.325) 7(1.293,0.325) 8(1.293,0.975)
  rect 1.2x2 smd paste+0 mask+0.051: 9(0,0)
  silkscreen extent -1.57,-1.68 1.57,1.68, body extent -1.45,-1.55 1.45,1.55, height 1.5
SOT_2815,115_NXP [mm]
  rect 0.782x0.355 smd paste+0 mask+0.051: 1(-1.064,0.65) 2(-1.064,0) 3(-1.064,-0.65) 4(1.064,-0.65) 5(1.064,0) 6(1.064,0.65)
  silkscreen extent -0.8,-1.23 0.8,1.23, body extent -1.1,-1.1 1.1,1.1, height 1.09
TP_2X1.8 [mm]
  rect 1.8x2 smd mask+0.051: 1(0,0)
  body extent -0.89,-0.99 0.89,0.99, height 0.03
